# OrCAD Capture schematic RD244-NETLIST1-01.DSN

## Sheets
1 7: size Custom
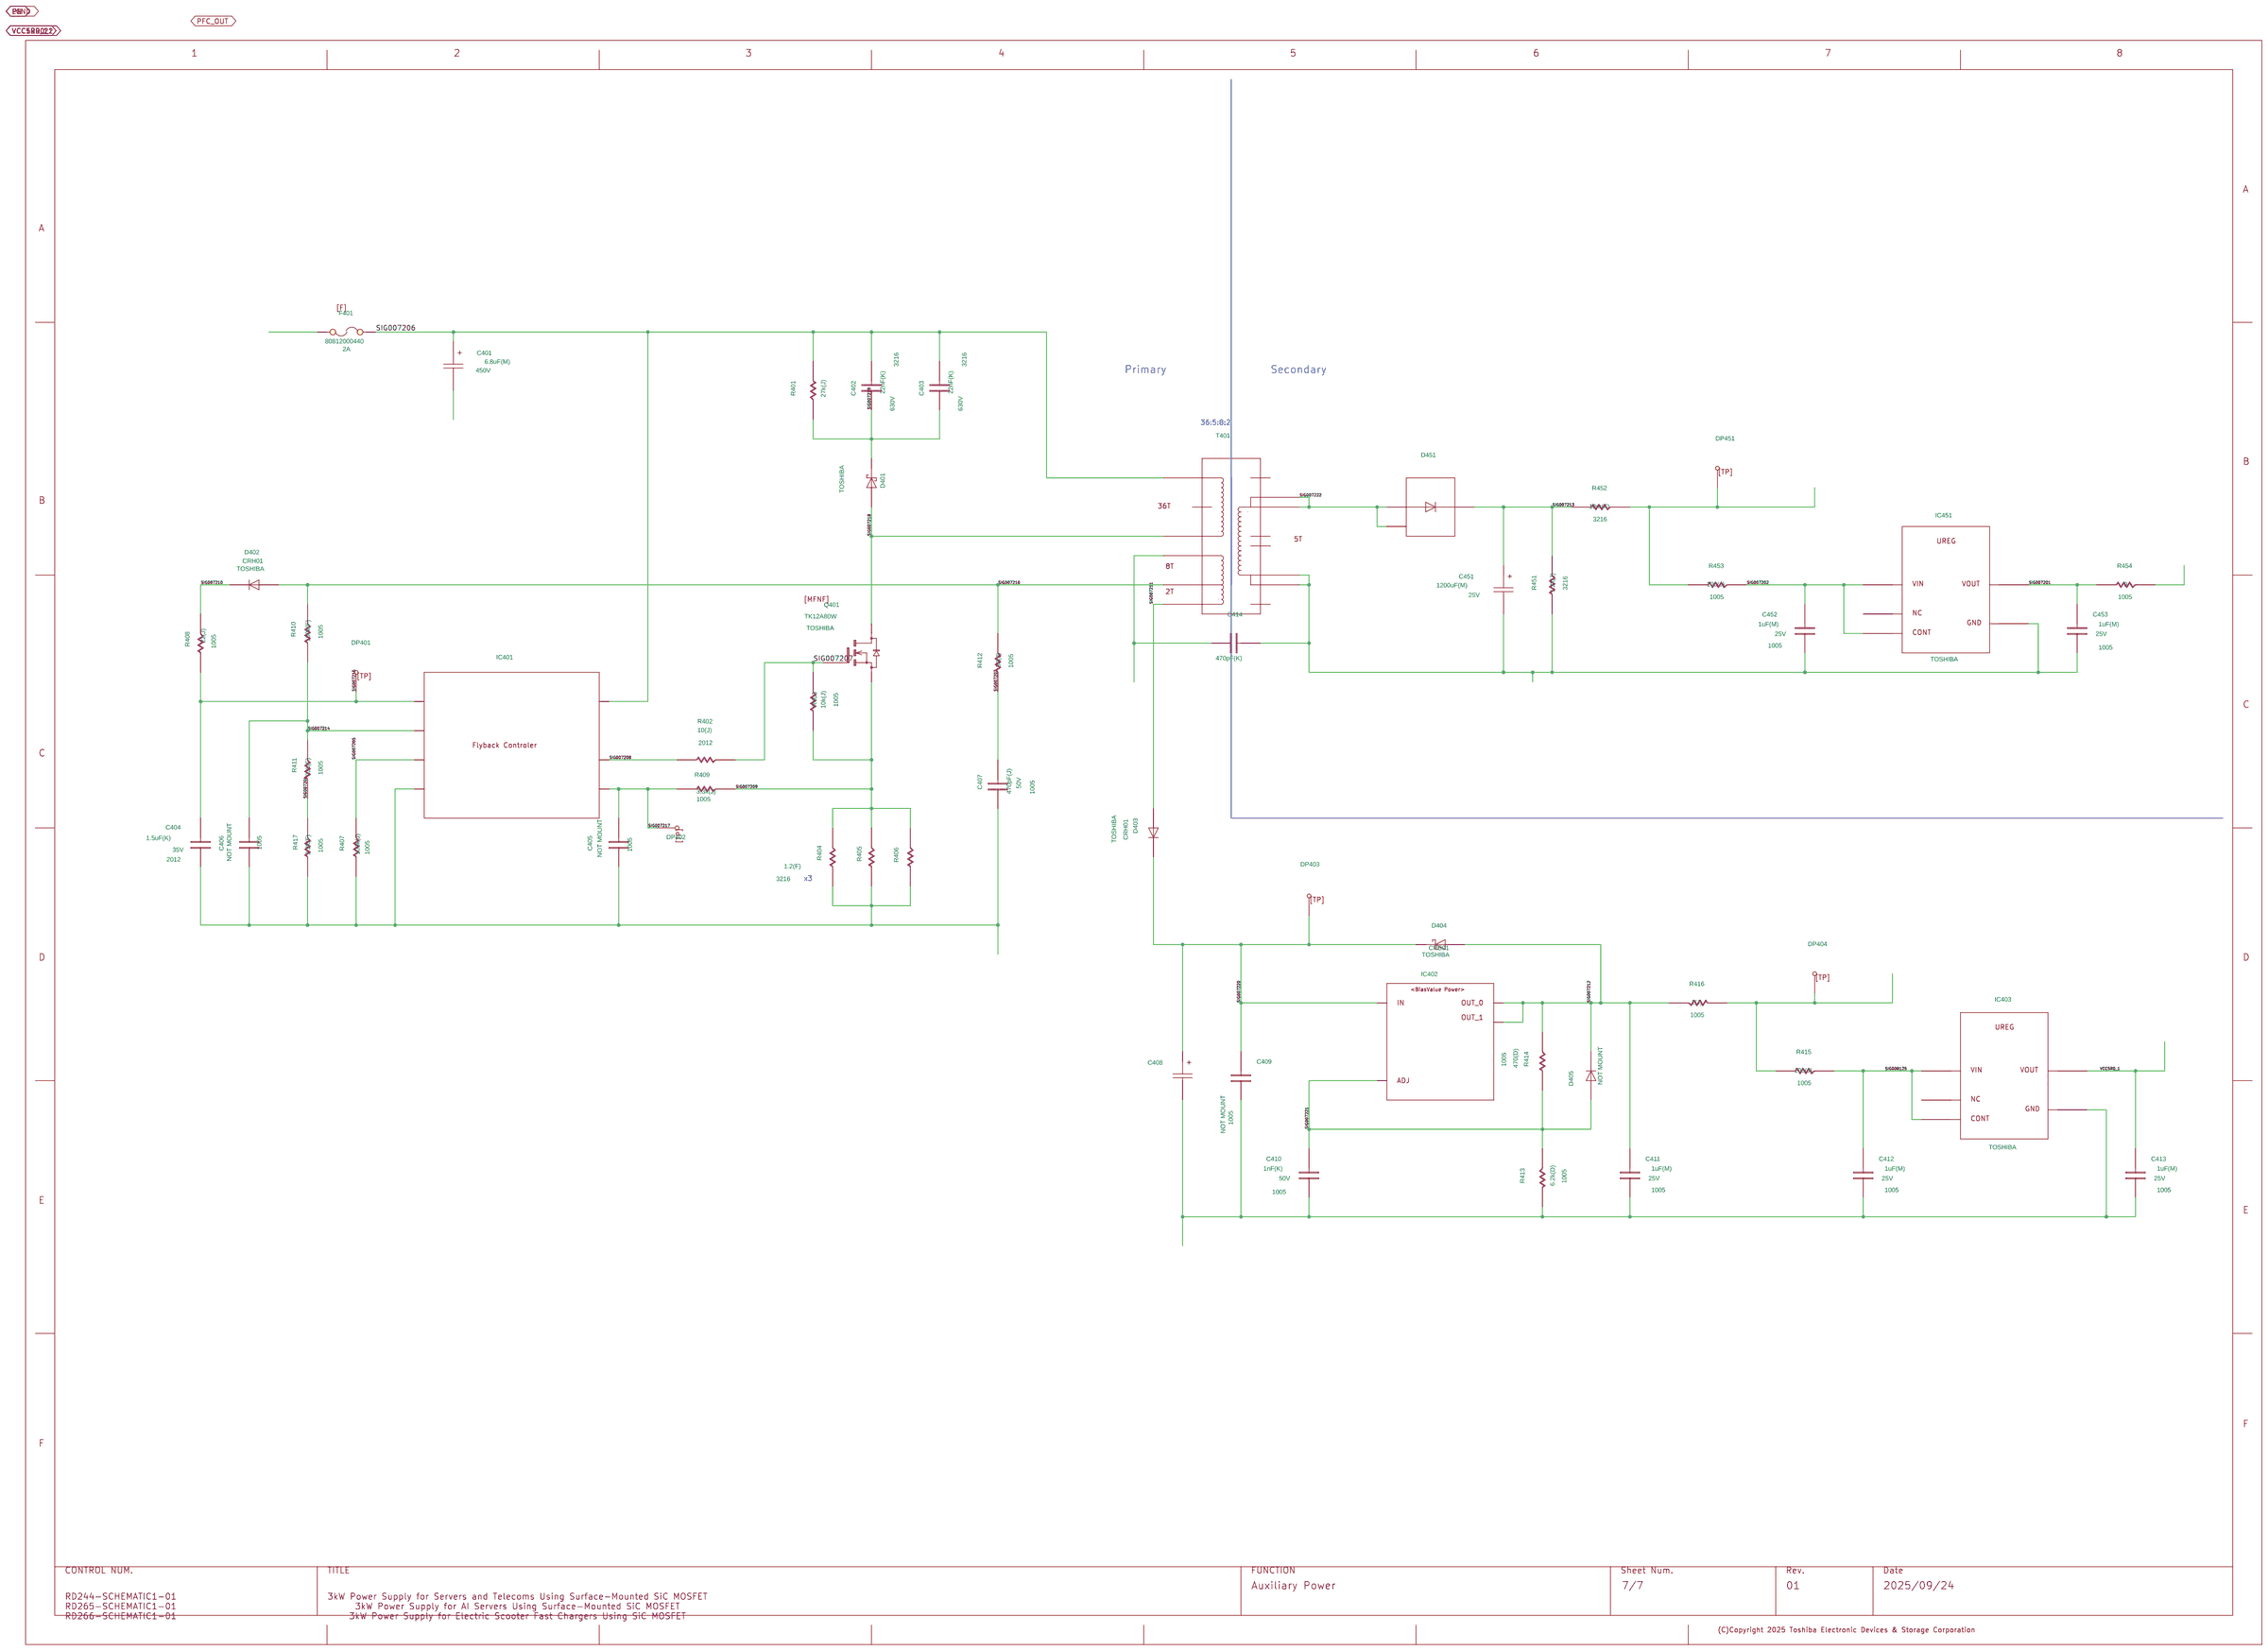
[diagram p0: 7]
2 6: size Custom
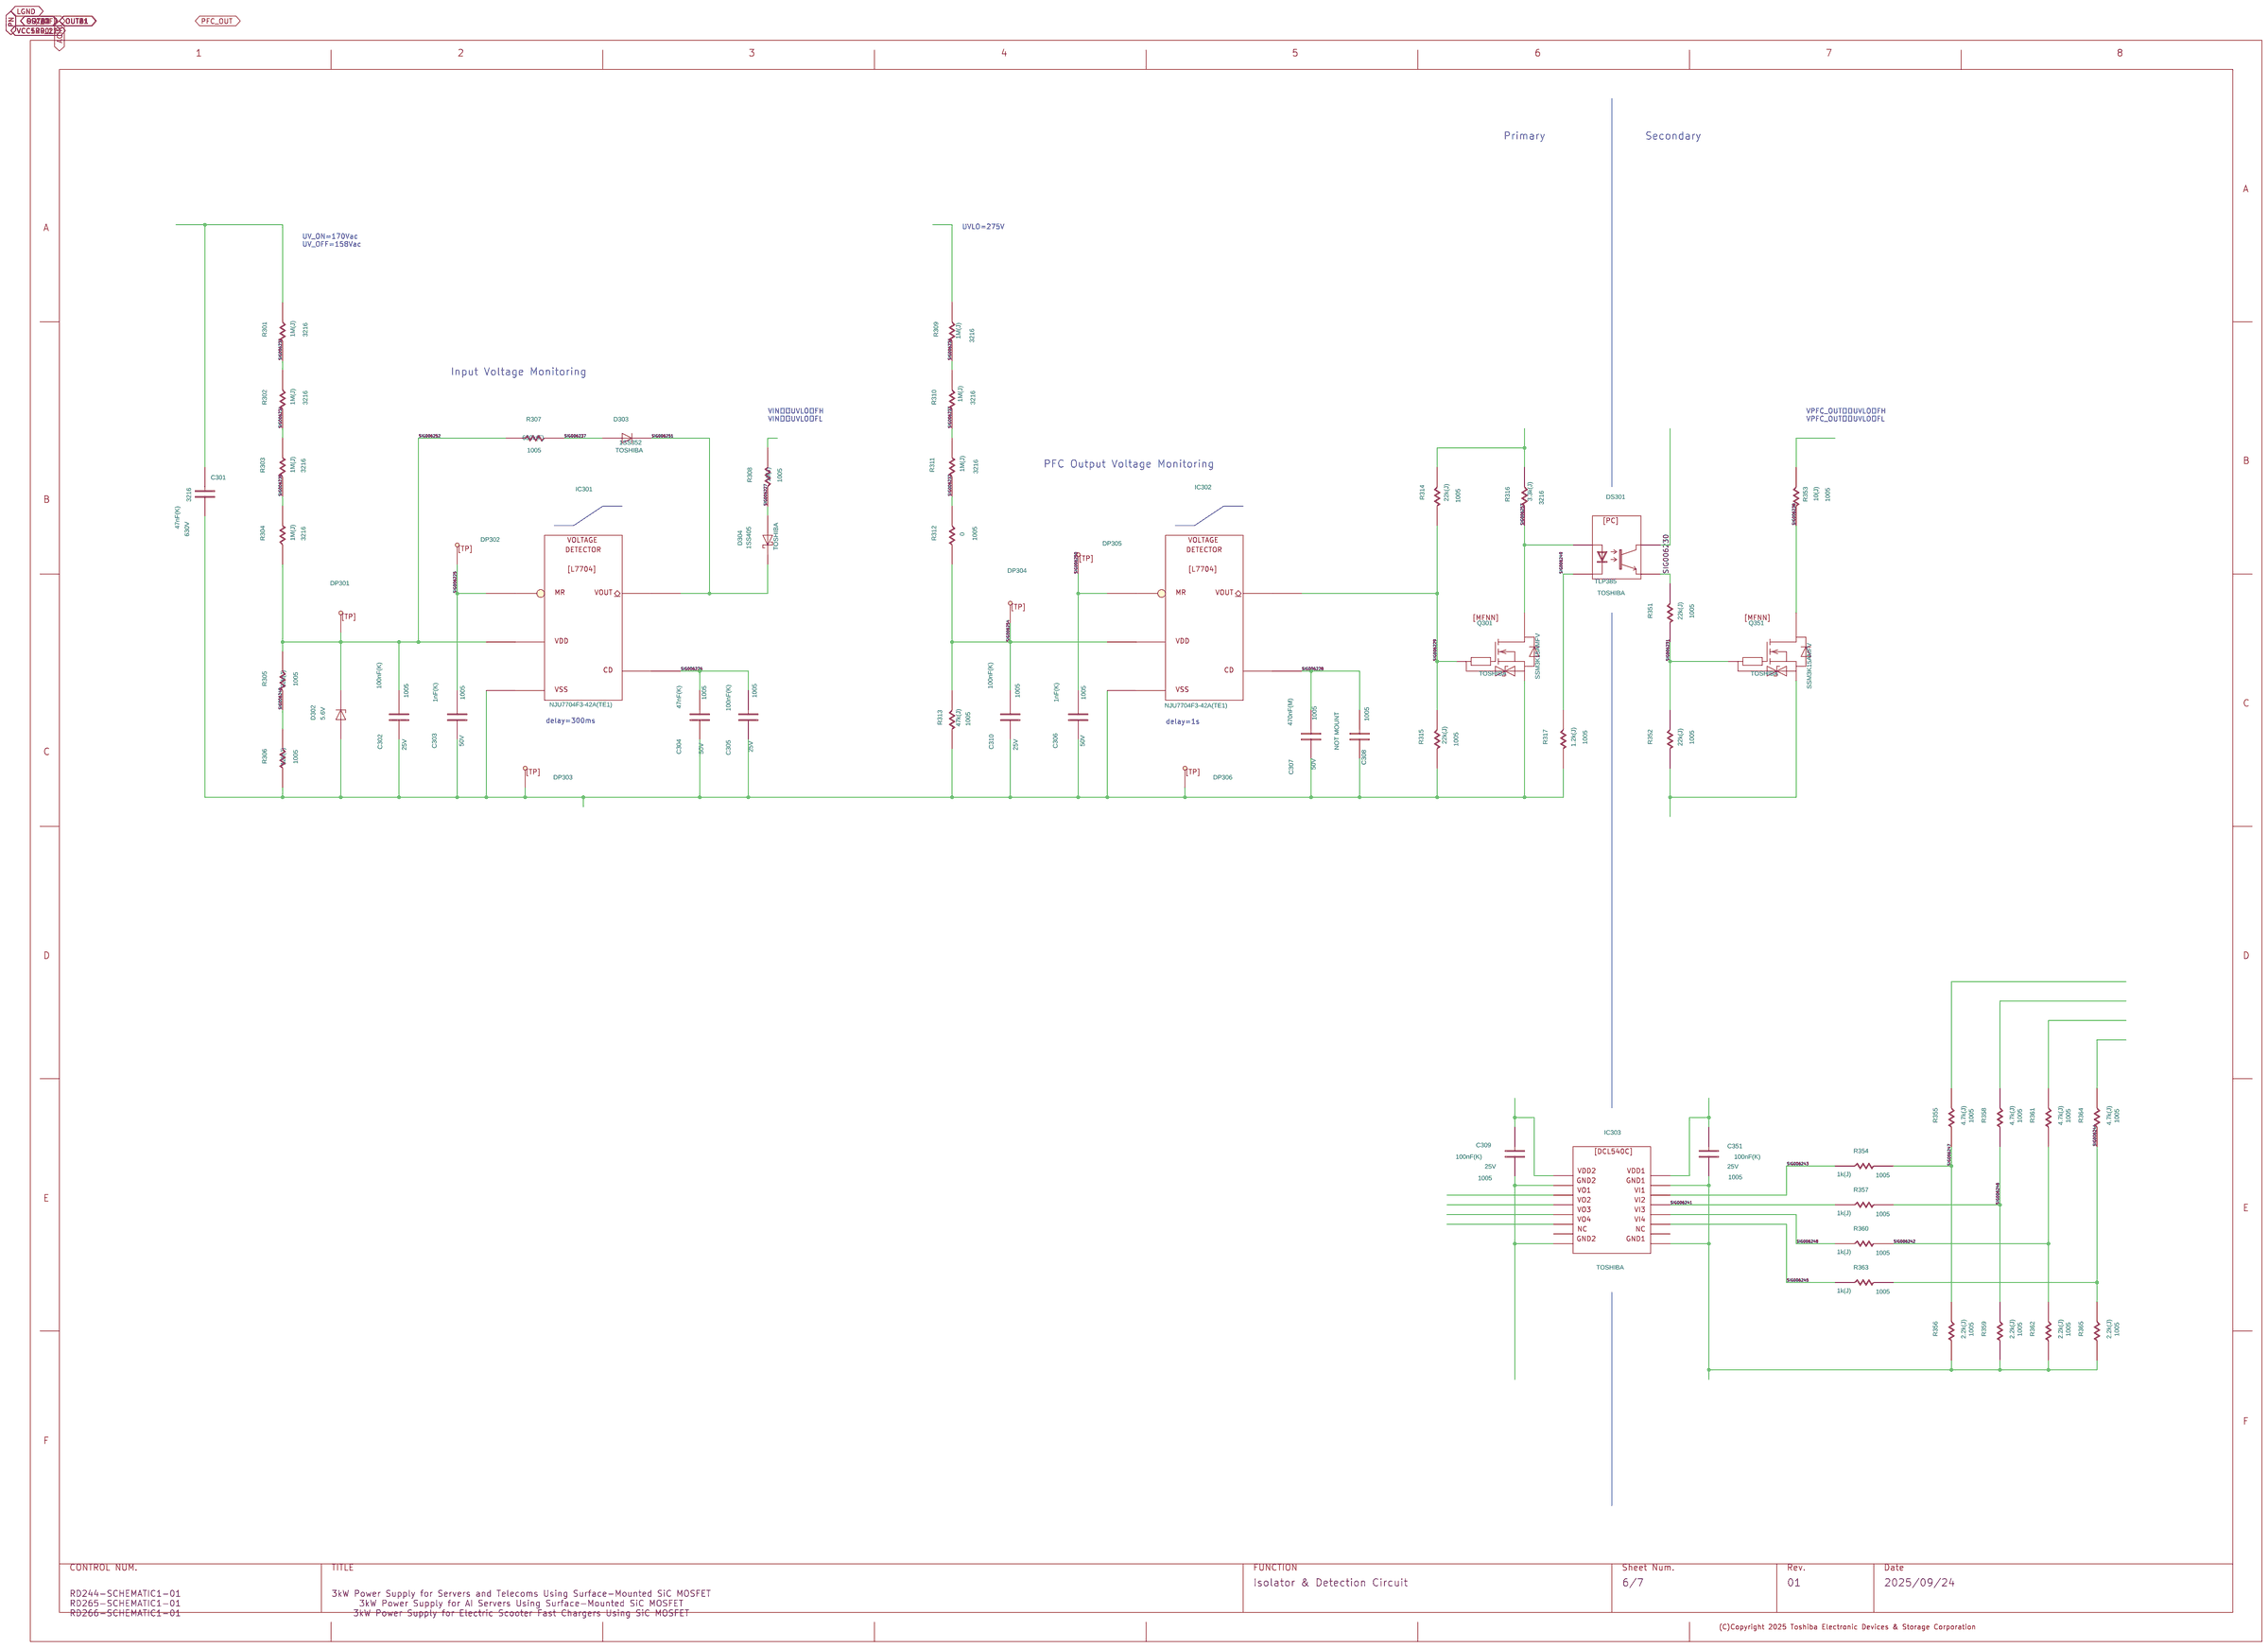
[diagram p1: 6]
3 5: size Custom
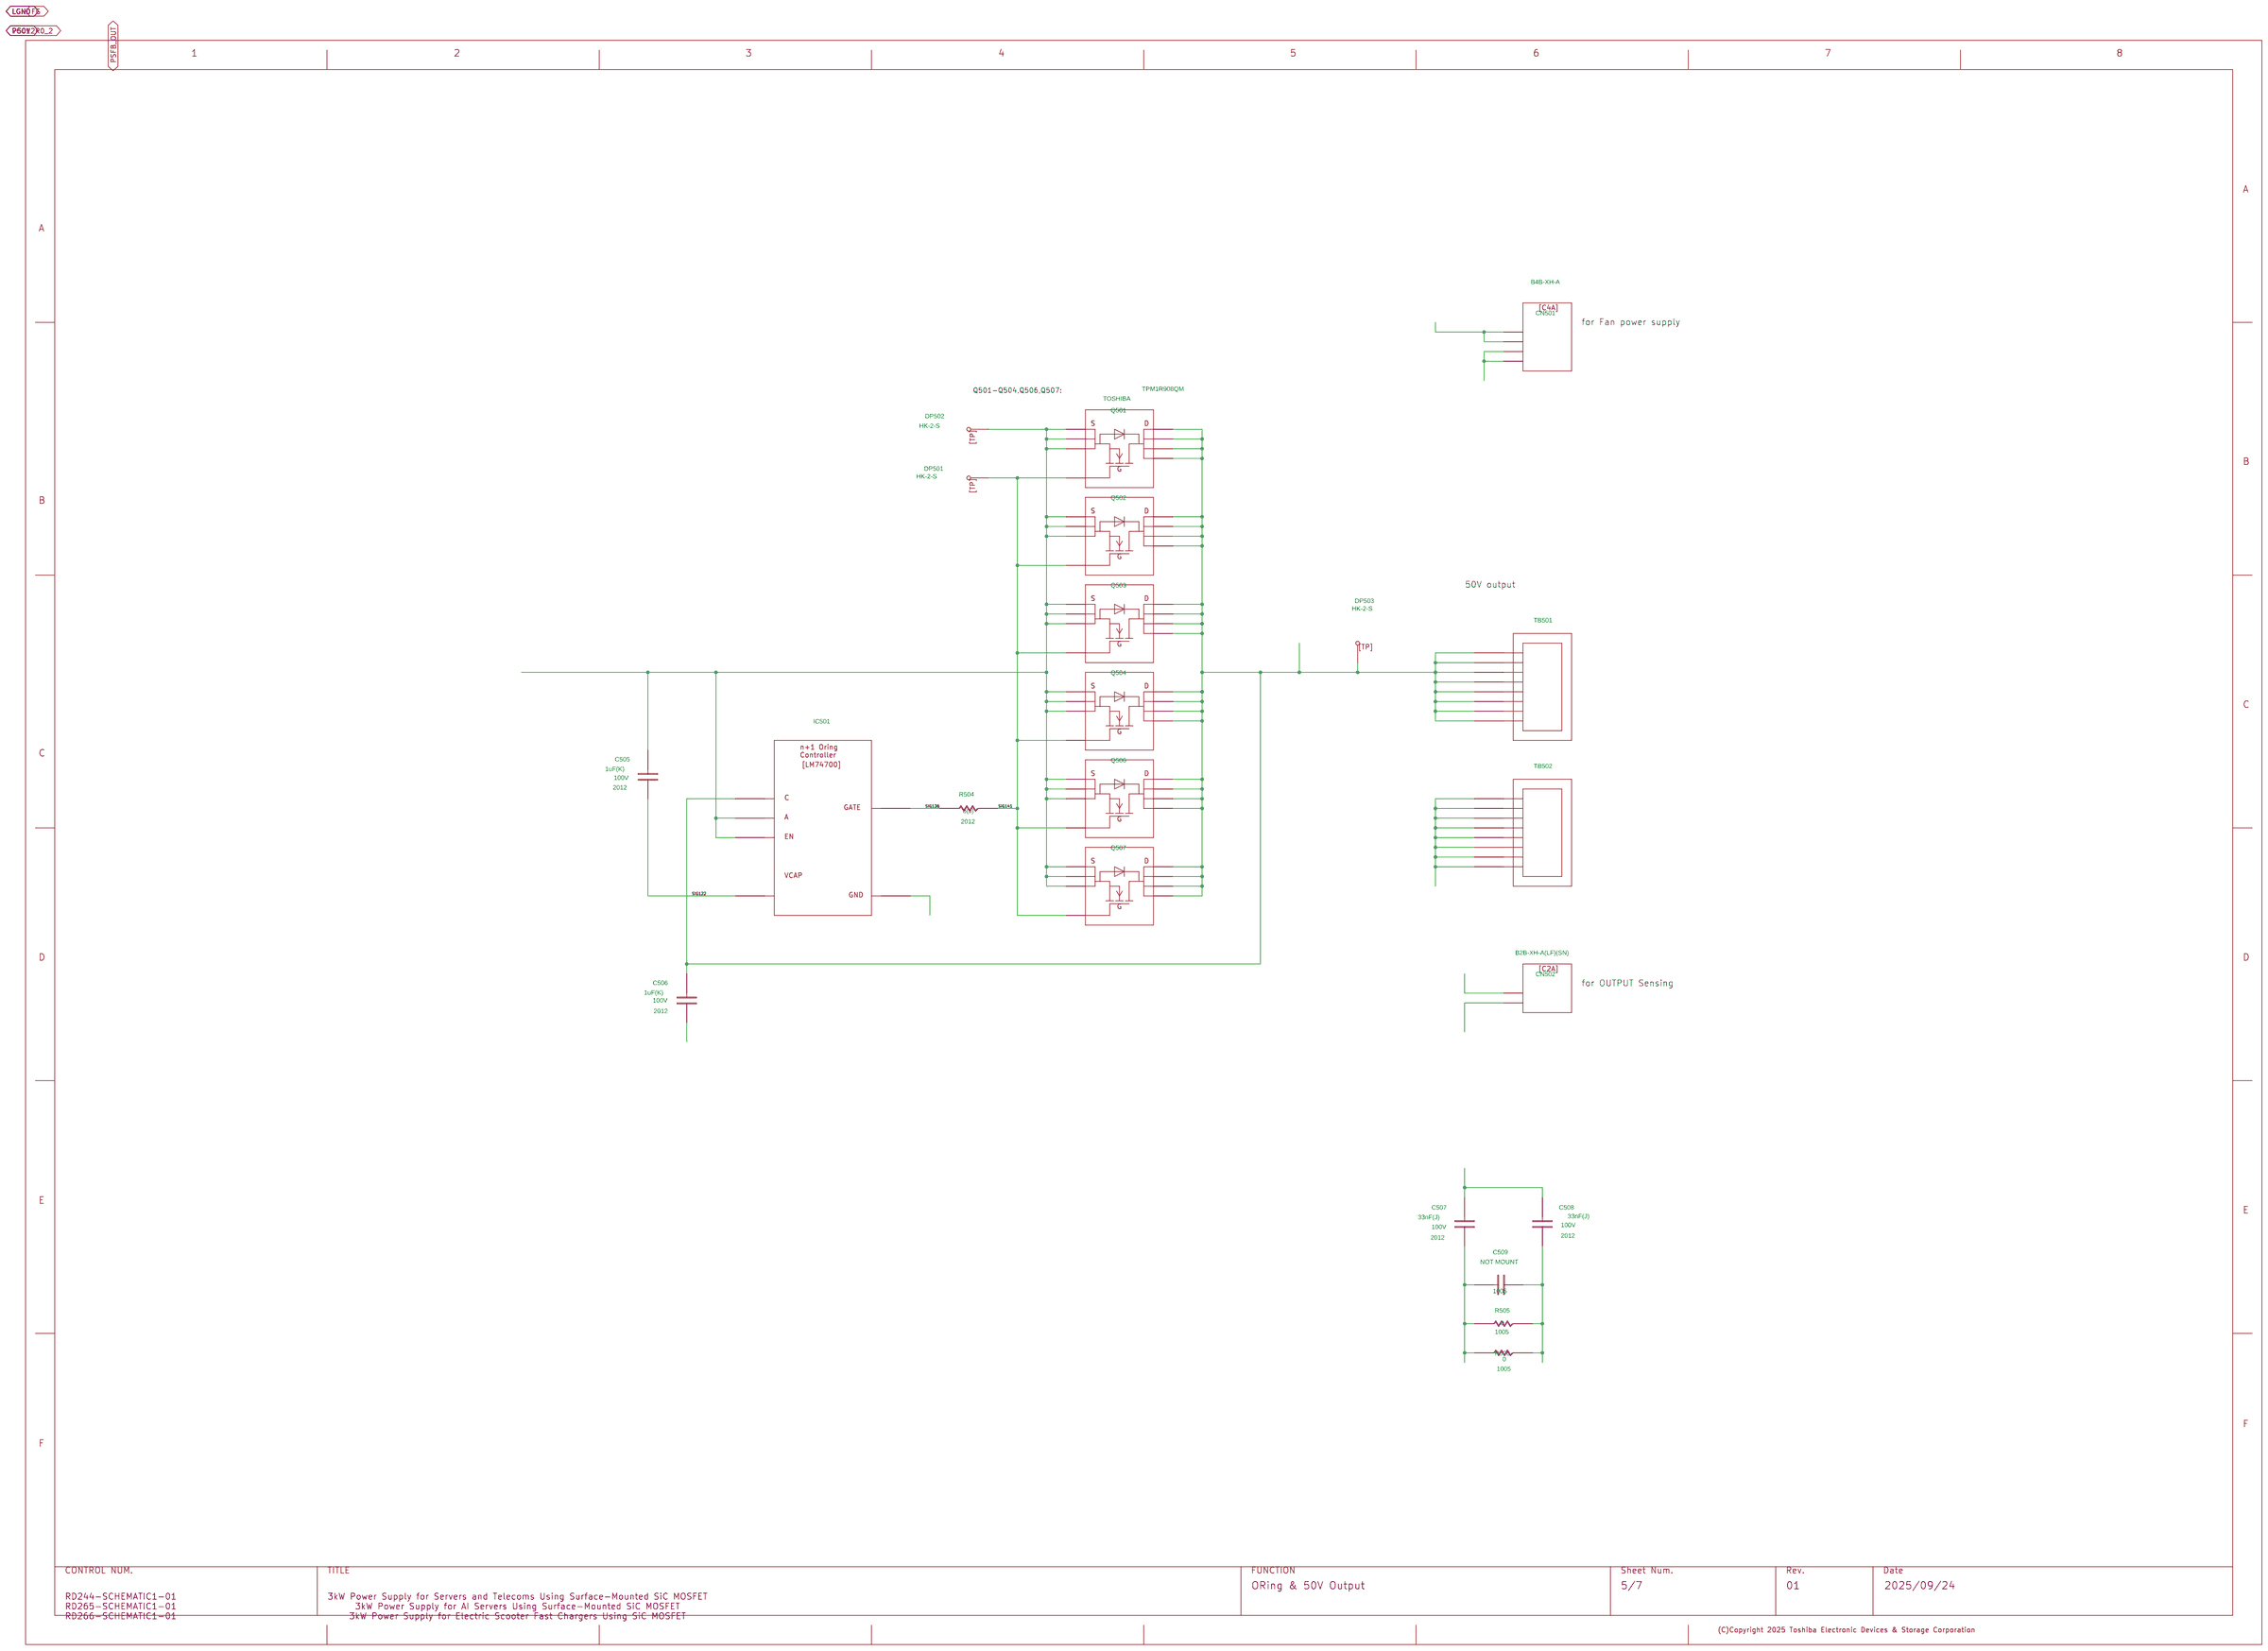
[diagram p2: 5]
4 4: size Custom
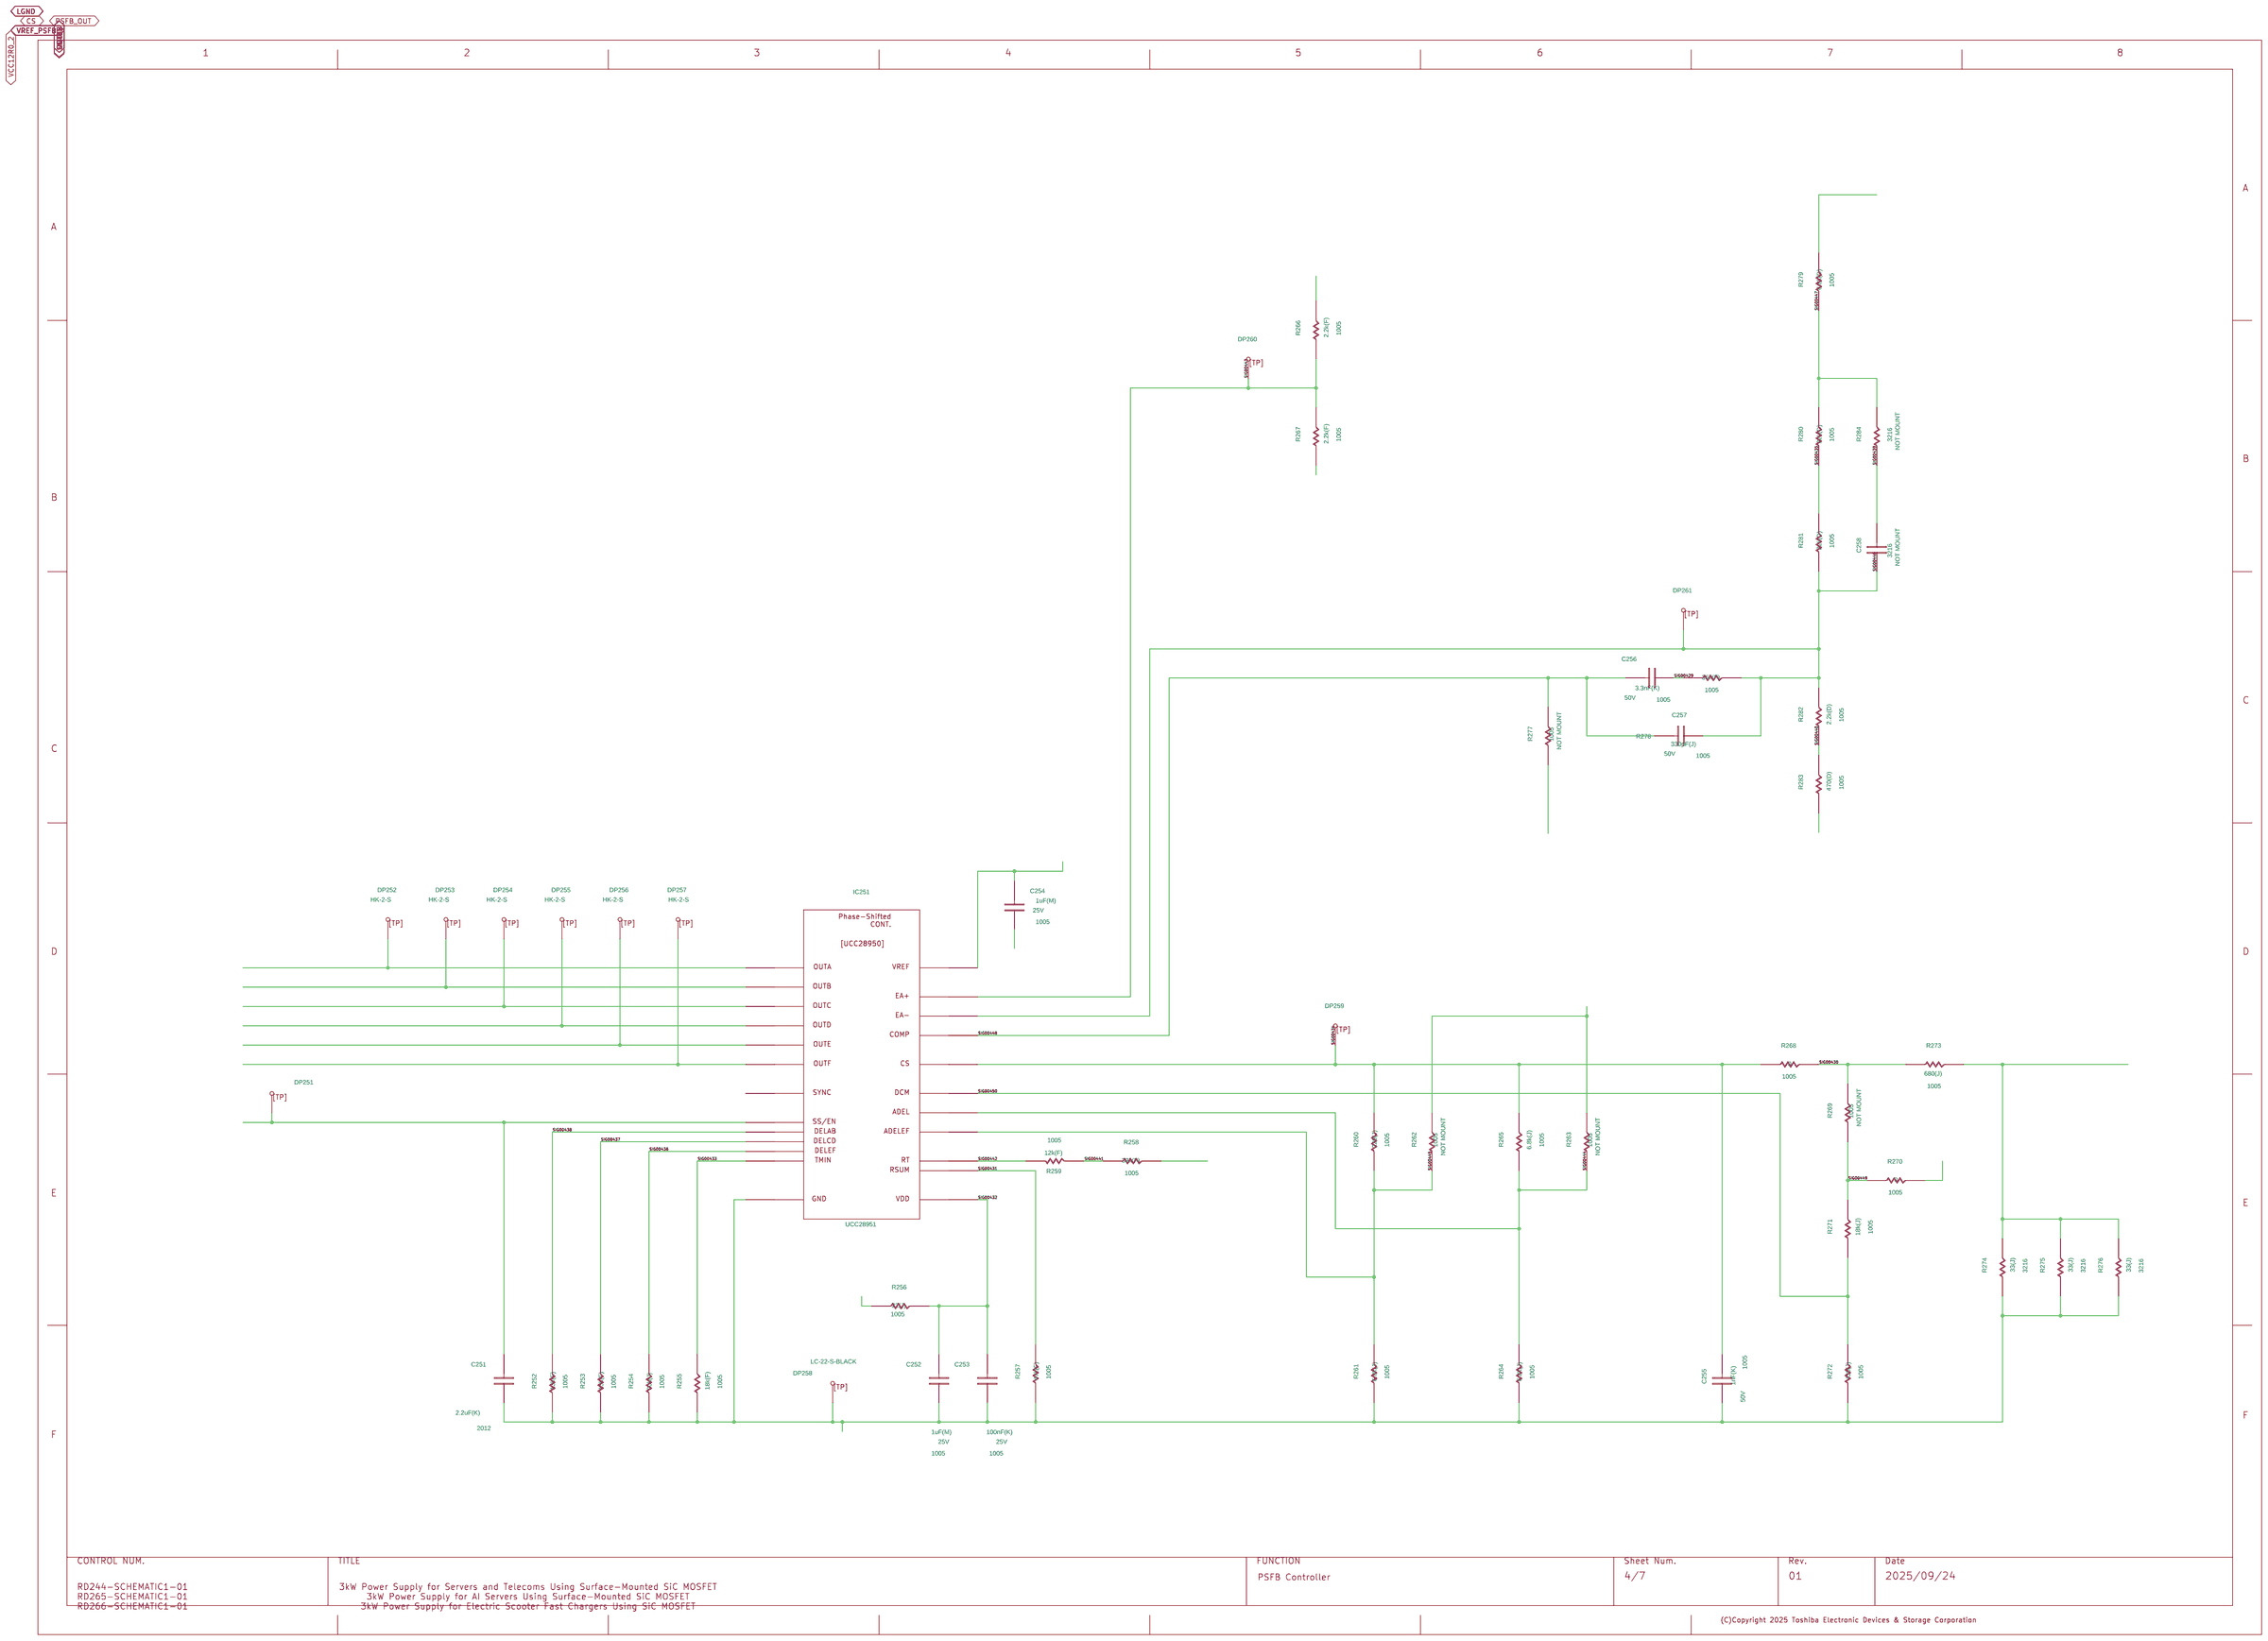
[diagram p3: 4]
5 3: size Custom
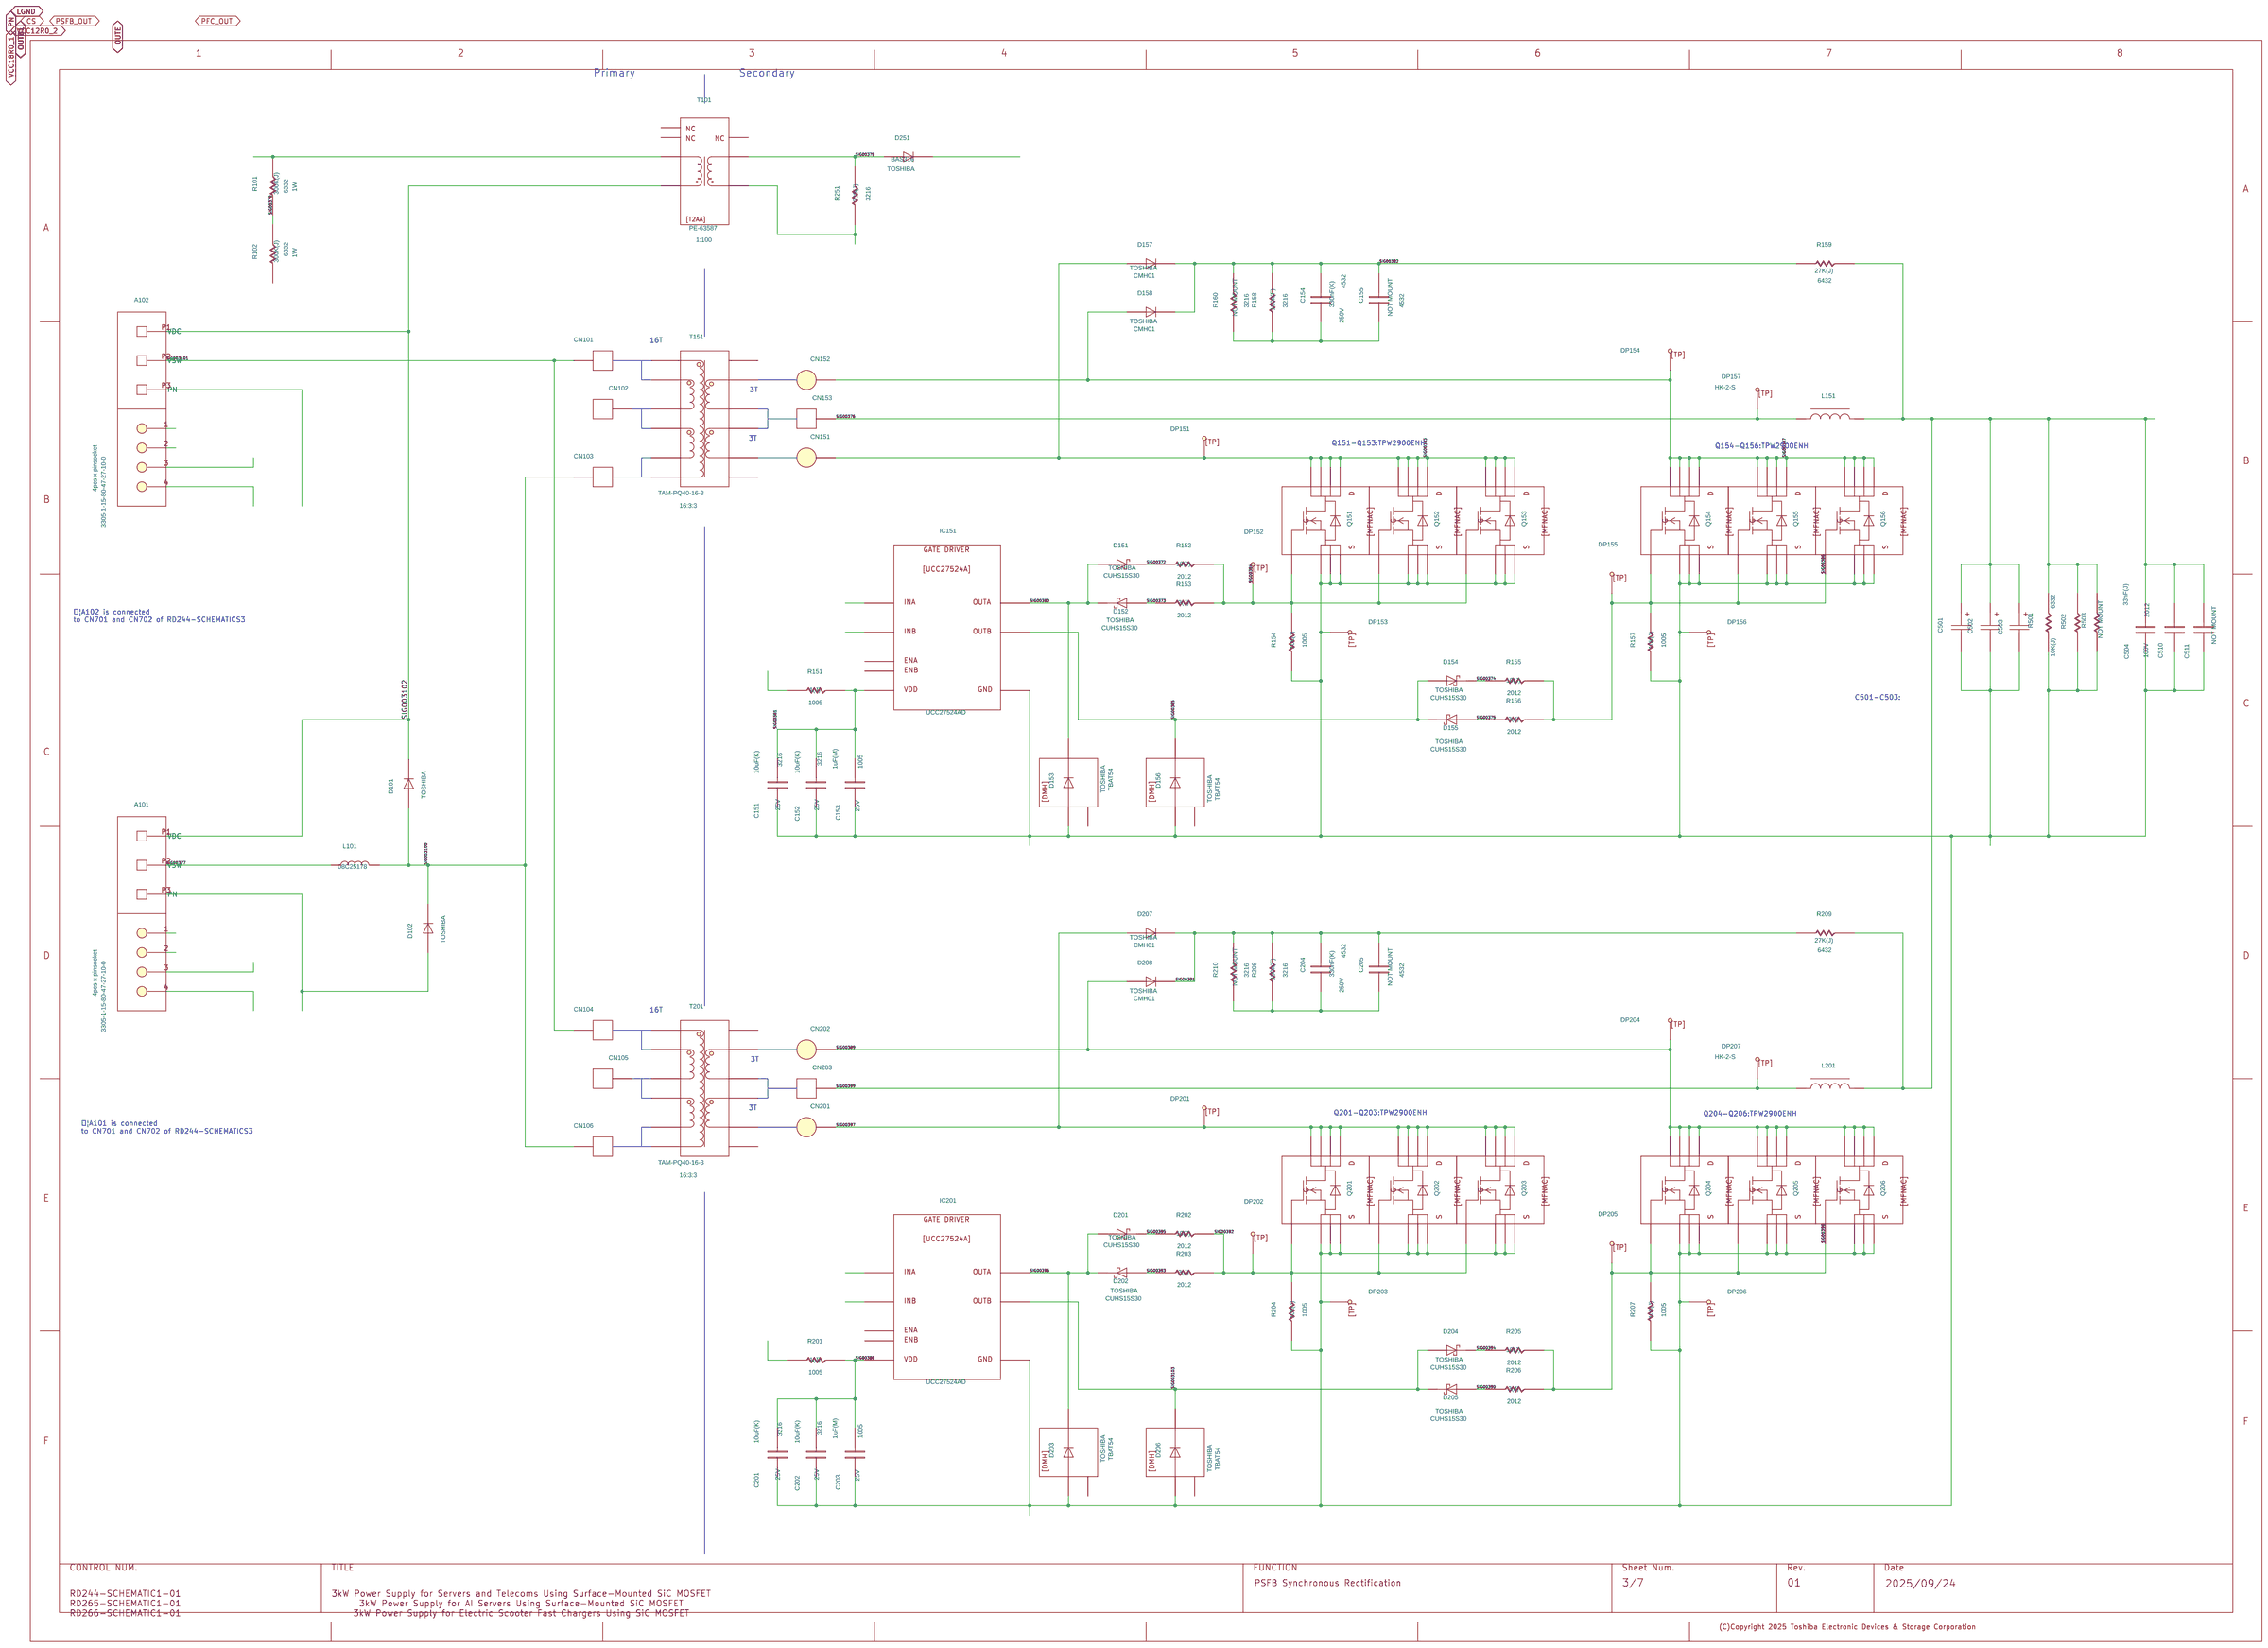
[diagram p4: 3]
6 2: size Custom
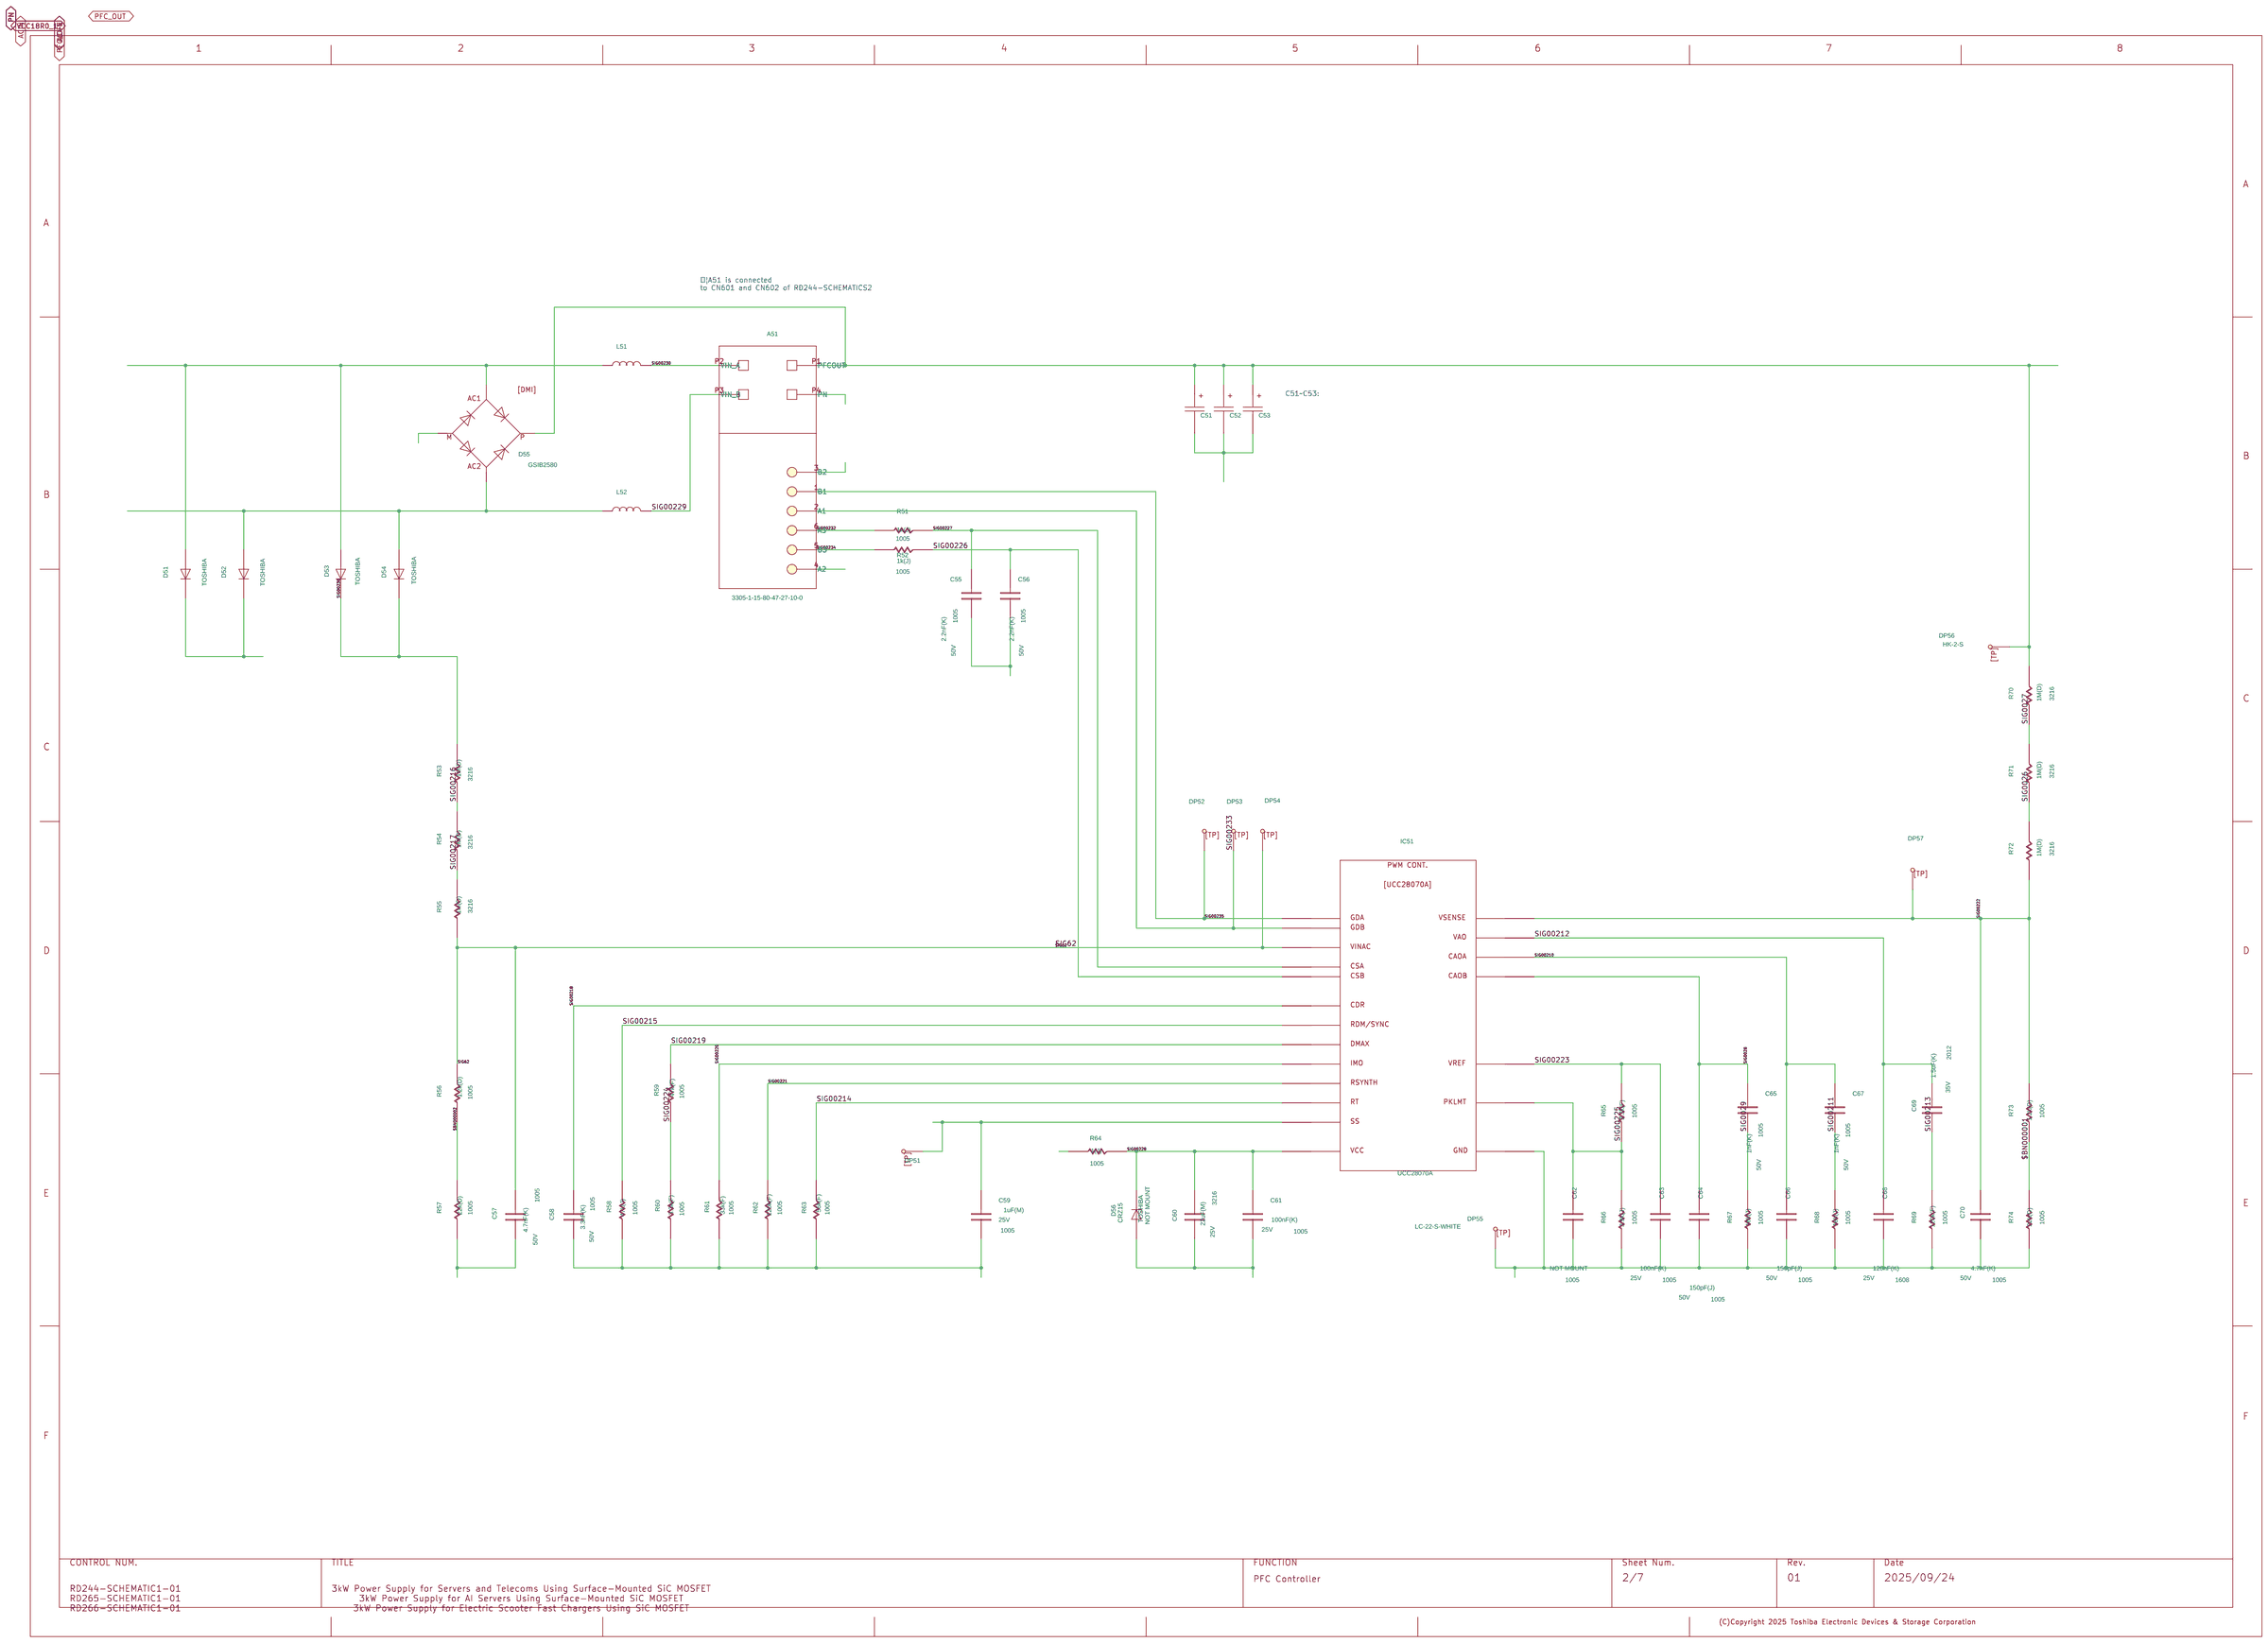
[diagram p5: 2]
7 1: size Custom
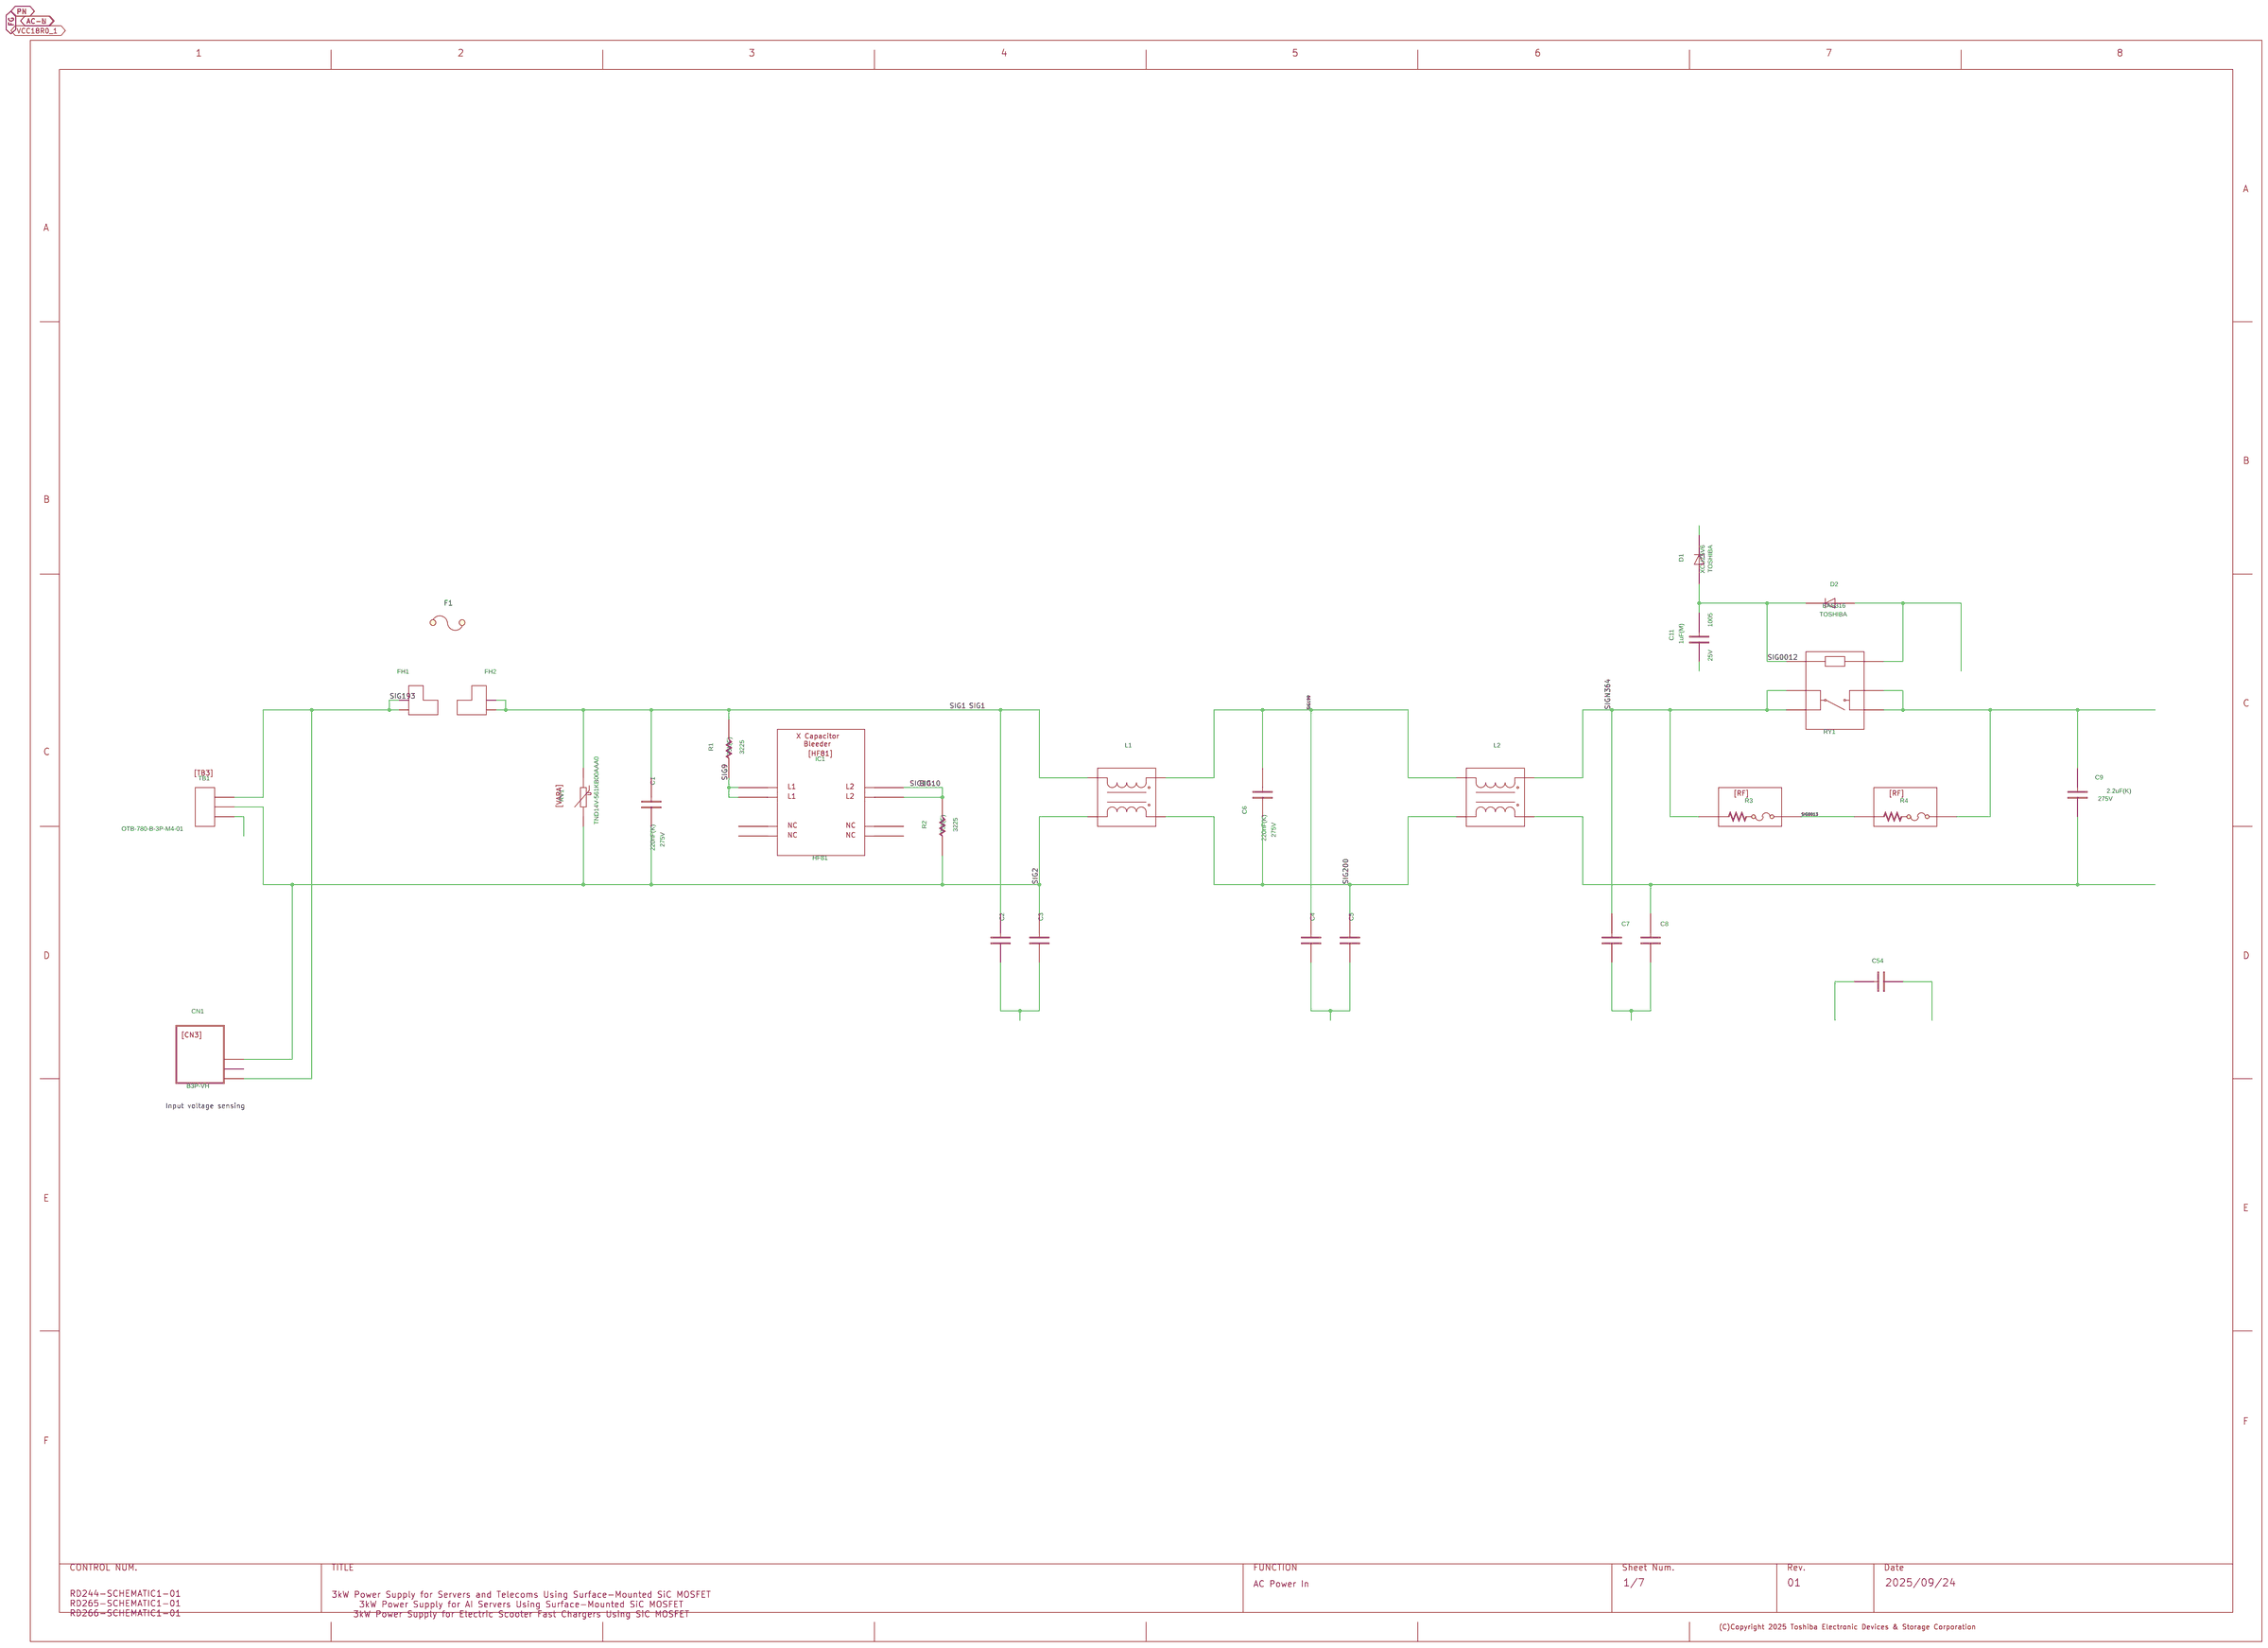
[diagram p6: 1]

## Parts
sheet 1
C1  C
C2  DE2B3SA101KA3BT02F
C3  DE2B3SA101KA3BT02F
C4  DE2E3SA222MN3AT02F
C5  DE2E3SA222MN3AT02F
C6  C
C7  DE2E3SA222MN3AT02F
C8  DE2E3SA222MN3AT02F
C9  C
C11  C
C54  DE2B3SA221KA3BT02F
CN1  CN3
D1  ZENERDIODE_USC-01
D2  D
F1  -
FH1  01220083Z
FH2  01220083Z
IC1  L81
L1  LDFW021252YBUV0E
L2  LDFW021252YBUV0E
R1  R
R2  R
R3  Y5JA-330JPTL3_5
R4  Y5JA-330JPTL3_5
RV1  VARA
RY1  G2RL-1A-E2-CV-HA
TB1  TB3
U?#6  WAKU_DEF_A3_1
sheet 2
A51  RD-244_PFC_UNIT1
C51  EKHE421VSN102MA45Z
C52  EKHE421VSN102MA45Z
C53  EKHE421VSN102MA45Z
C55  C
C56  C
C57  C
C58  C
C59  C
C60  C
C61  C
C62  C
C63  C
C64  C
C65  C
C66  C
C67  C
C68  C
C69  GRM21BC71E106KE01
C70  C
D51  CRG04A
D52  CRG04A
D53  CRG04A
D54  CRG04A
D55  DMI
D56  ZD
DP51  TP
DP52  TP
DP53  TP
DP54  TP
DP55  TP
DP56  TP
DP57  TP
IC51  L28070
L51  TAM-30A131
L52  TAM-30A131
R51  R
R52  R
R53  R
R54  R
R55  R
R56  R
R57  R
R58  R
R59  R
R60  R
R61  R
R62  R
R63  R
R64  R
R65  R
R66  R
R67  R
R68  R
R69  R
R70  R
R71  R
R72  R
R73  R
R74  R
U?#5  WAKU_DEF_A3_1
sheet 3
A101  RD-244_FB_UNIT
A102  RD-244_FB_UNIT
C151  C
C152  C
C153  C
C154  C
C155  C
C201  C
C202  C
C203  C
C204  C
C205  C
C501  CP
C502  CP
C503  CP
C504  GRM21BC71E106KE01
C510  GRM21BC71E106KE01
C511  GRM21BC71E106KE01
CN101  LONGHOLE_2R5-5R5
CN102  LONGHOLE_2R5-4R5
CN103  LONGHOLE_2R5-5R5
CN104  LONGHOLE_2R5-5R5
CN105  LONGHOLE_2R5-4R5
CN106  LONGHOLE_2R5-5R5
CN151  TH_PHI_4R5
CN152  TH_PHI_4R5
CN153  LONGHOLE_4R5-8R5
CN201  TH_PHI_4R5
CN202  TH_PHI_4R5
CN203  LONGHOLE_4R5-8R5
D101  TRS8E65F
D102  TRS8E65F
D151  CUHS15S30
D152  CUHS15S30
D153  DMH
D154  CUHS15S30
D155  CUHS15S30
D156  DMH
D157  D
D158  D
D201  CUHS15S30
D202  CUHS15S30
D203  DMH
D204  CUHS15S30
D205  CUHS15S30
D206  DMH
D207  D
D208  D
D251  D
DP151  TP
DP152  TP
DP153  TP
DP154  TP
DP155  TP
DP156  TP
DP157  TP
DP201  TP
DP202  TP
DP203  TP
DP204  TP
DP205  TP
DP206  TP
DP207  TP
IC151  L27524
IC201  L27524
L101  TMSD-Y3001
L151  TAM-CTW32A6R5
L201  TAM-CTW32A6R5
Q151  TPH2R408QM_8PIN
Q152  TPH2R408QM_8PIN
Q153  TPH2R408QM_8PIN
Q154  TPH2R408QM_8PIN
Q155  TPH2R408QM_8PIN
Q156  TPH2R408QM_8PIN
Q201  TPH2R408QM_8PIN
Q202  TPH2R408QM_8PIN
Q203  TPH2R408QM_8PIN
Q204  TPH2R408QM_8PIN
Q205  TPH2R408QM_8PIN
Q206  TPH2R408QM_8PIN
R101  R
R102  R
R151  R
R152  R
R153  R
R154  R
R155  R
R156  R
R157  R
R158  R
R159  R
R160  R
R201  R
R202  R
R203  R
R204  R
R205  R
R206  R
R207  R
R208  R
R209  R
R210  R
R251  R
R501  R
R502  R
R503  R
T101  T2AA
T151  T3_12V67A
T201  T3_12V67A
U?#4  WAKU_DEF_A3_1
sheet 4
C251  GRM21BC71E106KE01
C252  C
C253  C
C254  C
C255  C
C256  C
C257  C
C258  C
DP251  TP
DP252  TP
DP253  TP
DP254  TP
DP255  TP
DP256  TP
DP257  TP
DP258  TP
DP259  TP
DP260  TP
DP261  TP
IC251  L28950
R252  R
R253  R
R254  R
R255  R
R256  R
R257  R
R258  R
R259  R
R260  R
R261  R
R262  R
R263  R
R264  R
R265  R
R266  R
R267  R
R268  R
R269  R
R270  R
R271  R
R272  R
R273  R
R274  R
R275  R
R276  R
R277  R
R278  R
R279  R
R280  R
R281  R
R282  R
R283  R
R284  R
U?#3  WAKU_DEF_A3_1
sheet 5
C505  GRM21BC71E106KE01
C506  GRM21BC71E106KE01
C507  GRM21BC71E106KE01
C508  GRM21BC71E106KE01
C509  C
CN501  C4A
CN502  C2A
DP501  TP
DP502  TP
DP503  TP
IC501  LM74700-Q1
Q501  NCHMOSFET_SOPADVANCE-E-01
Q502  NCHMOSFET_SOPADVANCE-E-01
Q503  NCHMOSFET_SOPADVANCE-E-01
Q504  NCHMOSFET_SOPADVANCE-E-01
Q506  NCHMOSFET_SOPADVANCE-E-01
Q507  NCHMOSFET_SOPADVANCE-E-01
R504  R
R505  R
R506  R
TB501  7460305
TB502  7460305
U?#2  WAKU_DEF_A3_1
sheet 6
C301  C
C302  C
C303  C
C304  C
C305  C
C306  C
C307  C
C308  C
C309  C
C310  C
C351  C
D302  ZENERDIODE_USC-01
D303  D
D304  1SS405
DP301  TP
DP302  TP
DP303  TP
DP304  TP
DP305  TP
DP306  TP
DS301  TLP385
IC301  L7704
IC302  L7704
IC303  DCL540C01
Q301  MFNN
Q351  MFNN
R301  R
R302  R
R303  R
R304  R
R305  R
R306  R
R307  R
R308  R
R309  R
R310  R
R311  R
R312  R
R313  R
R314  R
R315  R
R316  R
R317  R
R351  R
R352  R
R353  R
R354  R
R355  R
R356  R
R357  R
R358  R
R359  R
R360  R
R361  R
R362  R
R363  R
R364  R
R365  R
U?#1  WAKU_DEF_A3_1
sheet 7
C401  CP
C402  C
C403  C
C404  GRM21BC71E106KE01
C405  C
C406  C
C407  C
C408  EMLA350ARA331MJA0G
C409  C
C410  C
C411  C
C412  C
C413  C
C414  DE2B3SA221KA3BT02F
C451  CP
C452  C
C453  C
D401  CRF03A
D402  D
D403  D
D404  SBD
D405  D
D451  RF501BGE2S
DP401  TP
DP402  TP
DP403  TP
DP404  TP
DP451  TP
F401  F
IC401  UCC28711
IC402  LM317_TRANS  [DCY0004A_N]
IC403  TCR1HF50B
IC451  TCR1HF50B
Q401  MFNF
R401  R
R402  R
R403  R
R404  R
R405  R
R406  R
R407  R
R408  R
R409  R
R410  R
R411  R
R412  R
R413  R
R414  R
R415  R
R416  R
R417  R
R451  R
R452  R
R453  R
R454  R
T401  T3_12V67A
U?#7  WAKU_DEF_A3_1

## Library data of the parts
C1 C6 = C: COMP: PRT_17; COMPONENTTYPE: 4; GCOUNT: 1; MAXGCOUNT: 1; SAVECOUNT: 0; SIZECODESMD: DIP; VAL1: 220nF(K); VAL2: 275V
C2 C3 = DE2B3SA101KA3BT02F: CHIPSIZE: [hsb`7.5mmió]; COMPONENTTYPE: 4; GCOUNT: 1; MAXGCOUNT: 1; SIZECODESMD: DIP
C4 C7 C8 = DE2E3SA222MN3AT02F: CHIPSIZE: [hsb`7.5mmió]; COMPONENTTYPE: 4; GCOUNT: 1; MAXGCOUNT: 1; SIZECODESMD: DIP
C5 = DE2E3SA222MN3AT02F: ADSCNVFLAG: ON; CHIPSIZE: [hsb`7.5mmió]; COMPONENTTYPE: 4; GCOUNT: 1; ICX_PART_MODEL: CON_2.2N; MAXGCOUNT: 1; SIZECODESMD: DIP; SQ_PART_MODEL: CON_2.2N
C9 = C: COMP: PRT_18; COMPONENTTYPE: 4; GCOUNT: 1; MAXGCOUNT: 1; SAVECOUNT: 0; SIZECODESMD: DIP; VAL1: 2.2uF(K); VAL2: 275V
C11 C59 C153 C203 C252 C254 = C: CHIPSIZE: 1005; COMP: PRT_52; COMPONENTTYPE: 4; GCOUNT: 1; MAXGCOUNT: 1; SAVECOUNT: 0; SIZECODESMD: 1005; VAL1: 1uF(M); VAL2: 25V
C54 = DE2B3SA221KA3BT02F: COMPONENTTYPE: 4; GCOUNT: 1; MAXGCOUNT: 1; SIZECODESMD: DIP
CN1 = CN3: ADSCNVFLAG: ON; CDBNAME: G36220401068; COMP: G36220401068; COMPONENTNAME: G36220401068_package; COMPONENTTYPE: 4; FUNCN: G36220401068; GCOUNT: 1; MAXGCOUNT: 1; SAVECOUNT: 0; USERCOMPTEXT3: [JCY; VAL3: B3P-VH
D1 = ZENERDIODE_USC-01: ADSCNVFLAG: ON; ADSCOMPONENTNAME: D_ZD; COMPONENTTYPE: 4; GCOUNT: 1; MAXGCOUNT: 1; USERCOMPTEXT3: TOSHIBA; VAL1: 5.6V; VAL3: XCUZ5V6
D2 = D: COMP: PRT_26; COMPONENTTYPE: 4; GCOUNT: 1; MAXGCOUNT: 1; USERCOMPTEXT2: 100V,0.25A; USERCOMPTEXT3: TOSHIBA; VAL3: BAS316
F1 = 0326030.MXP: COMPONENTTYPE: 4
FH1 FH2 = 01220083Z: COMPONENTTYPE: 4
IC1 = L81: COMP: PRT_45; COMPONENTTYPE: 4; VAL3: HF81
L1 L2 = LDFW021252YBUV0E: COMPONENTTYPE: 4
R1 R2 = R: CHIPSIZE: 3225; COMP: PRT_23; COMPONENTTYPE: 4; GCOUNT: 1; MAXGCOUNT: 1; SAVECOUNT: 0; SIZECODESMD: 3225; VAL1: 75k(F); VAL2: 500mW
R3 R4 = Y5JA-330JPTL3_5: CHIPSIZE: 13x9xH25.5; COMPONENTTYPE: 4; GCOUNT: 1; MAXGCOUNT: 1
RV1 = VARA: COMP: PRT_37; COMPONENTTYPE: 4; GCOUNT: 1; MAXGCOUNT: 1; VAL1: 560V; VAL3: TND14V-561KB00AAA0
RY1 = G2RL-1A-E2-CV-HA: COMPONENTTYPE: 4; GCOUNT: 1; MAXGCOUNT: 1; SAVEAREA0: -9347,-440,34039,23986; USERCOMPTEXT1: 23A
TB1 = TB3: ADSCNVFLAG: ON; COMP: K29S000A; COMPONENTTYPE: 4; GCOUNT: 1; MAXGCOUNT: 1; USERCOMPTEXT3: [JCY; VAL3: OTB-780-B-3P-M4-01
U?#6 = WAKU_DEF_A3_1: COMPONENTTYPE: 2; DATE: 2025/09/24; DESIGNED: TOSHIBA; DRAWINGNUMBER: RD244-SCHEMATIC1-01 / RD265-SCHEMATIC1-01 / RD266-SCHEMATIC1-01; FUNCTION: AC Power In; PAGENUMBER: 1; REVISION: 01; SAVECOUNT: 3; SHEETNUMBER: 1/7; SHTSAVECOUNT: 118; TIME: 10:19:22; TITLE: 3kW Power Supply for Servers and Telecoms Using Surface-Mounted SiC MOSFET / 3kW Power Supply for AI Servers Using Surface-Mounted SiC MOSFET / 3kW Power Supply for Electric Scooter Fast Chargers Using SiC MOSFET; UPDATEDATE: 2025.9.25; UPDATETIME: 13:12:48; UPDATEUSER: t5459927
A51 = RD-244_PFC_UNIT1: COMPONENTTYPE: 4; VAL3: 3305-1-15-80-47-27-10-0
C51-C53 = EKHE421VSN102MA45Z: ADSCNVFLAG: ON; COMPONENTTYPE: 4; GCOUNT: 1; ICX_PART_MODEL: CON_390U; MAXGCOUNT: 1; SIZECODESMD: DIP; SQ_PART_MODEL: CON_390U
C55 = C: CHIPSIZE: 1005; COMP: PRT_52; COMPONENTTYPE: 4; GCOUNT: 1; MAXGCOUNT: 1; SAVECOUNT: 0; SIZECODESMD: 1005; VAL1: 2.2nF(K); VAL2: 50V
C56 = C: CHIPSIZE: 1005; COMP: PRT_52; COMPONENTTYPE: 4; GCOUNT: 1; MAXGCOUNT: 1; OLDCOMPONENTID: 99; SAVECOUNT: 0; SIZECODESMD: 1005; VAL1: 2.2nF(K); VAL2: 50V
C57 C70 = C: CHIPSIZE: 1005; COMP: PRT_52; COMPONENTTYPE: 4; GCOUNT: 1; MAXGCOUNT: 1; SAVECOUNT: 0; SIZECODESMD: 1005; VAL1: 4.7nF(K); VAL2: 50V
C58 = C: CHIPSIZE: 1005; COMP: PRT_52; COMPONENTTYPE: 4; GCOUNT: 1; MAXGCOUNT: 1; SAVECOUNT: 0; SIZECODESMD: 1005; VAL1: 3.3nF(K); VAL2: 50V
C60 = C: COMP: PRT_46; COMPONENTTYPE: 4; SAVECOUNT: 0; SIZECODESMD: 3216; VAL1: 22uF(M); VAL2: 25V
C61 C302 C305 C309 C310 C351 = C: ADSCNVFLAG: ON; ADSCOMPONENTNAME: C_1005; CHIPSIZE: 1005; COMP: PRT_52; COMPONENTTYPE: 4; GCOUNT: 1; ICX_PART_MODEL: CON_100N; MAXGCOUNT: 1; SAVECOUNT: 0; SIZECODESMD: 1005; SQ_PART_MODEL: CON_100N; VAL1: 100nF(K); VAL2: 25V
C62 C509 = C: CHIPSIZE: 1005; COMP: PRT_52; COMPONENTTYPE: 4; GCOUNT: 1; MAXGCOUNT: 1; NOTMOUNT: NOT MOUNT; SAVECOUNT: 0; SIZECODESMD: 1005; VAL1: 100nF(K); VAL2: 25V
C63 C253 = C: CHIPSIZE: 1005; COMP: PRT_52; COMPONENTTYPE: 4; GCOUNT: 1; MAXGCOUNT: 1; SAVECOUNT: 0; SIZECODESMD: 1005; VAL1: 100nF(K); VAL2: 25V
C64 C66 = C: CHIPSIZE: 1005; COMP: PRT_52; COMPONENTTYPE: 4; GCOUNT: 1; MAXGCOUNT: 1; SAVECOUNT: 0; SIZECODESMD: 1005; VAL1: 150pF(J); VAL2: 50V
C65 C67 C255 C303 C306 = C: CHIPSIZE: 1005; COMP: PRT_52; COMPONENTTYPE: 4; GCOUNT: 1; MAXGCOUNT: 1; SAVECOUNT: 0; SIZECODESMD: 1005; VAL1: 1nF(K); VAL2: 50V
C68 = C: CHIPSIZE: 1608; COMP: PRT_48; COMPONENTTYPE: 4; GCOUNT: 1; MAXGCOUNT: 1; SAVECOUNT: 0; SIZECODESMD: 1608; VAL1: 120nF(K); VAL2: 25V
C69 C404 = GRM21BC71E106KE01: CHIPSIZE: 1005; COMPONENTTYPE: 4; GCOUNT: 1; MAXGCOUNT: 1; SIZECODESMD: 2012; VAL1: 1.5uF(K); VAL2: 35V
D51-D54 = CRG04A: COMPONENTTYPE: 4; GCOUNT: 1; MAXGCOUNT: 1; USERCOMPTEXT2: 600V,1A; USERCOMPTEXT3: TOSHIBA
D55 = DMI: COMP: PRT_53; COMPONENTTYPE: 4; GCOUNT: 1; MAXGCOUNT: 1; VAL3: GSIB2580
D56 = ZD: COMP: PRT_6; COMPONENTTYPE: 4; GCOUNT: 1; MAXGCOUNT: 1; NOTMOUNT: NOT MOUNT; USERCOMPTEXT3: TOSHIBA; VAL1: CRZ15; VAL3: CRZ15
DP51-DP54 DP57 DP151-DP156 DP201-DP206 DP251 DP259-DP261 DP301-DP306 DP401-DP404 DP451 = TP: COMP: DTP815; COMPONENTTYPE: 4; USERCOMPTEXT1: ƒ³1.5mm
DP55 = TP: COMP: PRT_49; COMPONENTTYPE: 4; VAL3: LC-22-S-WHITE
DP56 DP157 DP207 DP252-DP257 DP501-DP503 = TP: COMP: PRT_44; COMPONENTTYPE: 4; VAL3: HK-2-S
IC51 = L28070: COMP: PRT_59; COMPONENTTYPE: 4; VAL3: UCC28070A
L51 L52 = TAM-30A131: COMPONENTTYPE: 4; GCOUNT: 1; MAXGCOUNT: 1
R51 = R: CHIPSIZE: 1608; COMP: GDM010004481; COMPONENTTYPE: 4; GCOUNT: 1; MAXGCOUNT: 1; OLDCOMPONENTID: 100; SAVECOUNT: 0; SIZECODESMD: 1005; VAL1: 1k(J); VAL2: 63mW
R52 R354 R357 R360 R363 = R: CHIPSIZE: 1608; COMP: GDM010004481; COMPONENTTYPE: 4; GCOUNT: 1; MAXGCOUNT: 1; SAVECOUNT: 0; SIZECODESMD: 1005; VAL1: 1k(J); VAL2: 63mW
R53-R55 R70-R72 = R: CHIPSIZE: 1608; COMP: PRT_5; COMPONENTTYPE: 4; GCOUNT: 1; MAXGCOUNT: 1; SAVECOUNT: 0; SIZECODESMD: 3216; VAL1: 1M(D); VAL2: 250mW
R56 R73 = R: CHIPSIZE: 1608; COMP: GDM010004481; COMPONENTTYPE: 4; GCOUNT: 1; MAXGCOUNT: 1; SAVECOUNT: 0; SIZECODESMD: 1005; VAL1: 1.2k(D); VAL2: 63mW
R57 R74 R280 R281 = R: CHIPSIZE: 1608; COMP: GDM010004481; COMPONENTTYPE: 4; GCOUNT: 1; MAXGCOUNT: 1; SAVECOUNT: 0; SIZECODESMD: 1005; VAL1: 22k(D); VAL2: 63mW
R58 R313 = R: CHIPSIZE: 1608; COMP: GDM010004481; COMPONENTTYPE: 4; GCOUNT: 1; MAXGCOUNT: 1; SAVECOUNT: 0; SIZECODESMD: 1005; VAL1: 47k(J); VAL2: 63mW
R59 R257 = R: CHIPSIZE: 1608; COMP: GDM010004481; COMPONENTTYPE: 4; GCOUNT: 1; MAXGCOUNT: 1; SAVECOUNT: 0; SIZECODESMD: 1005; VAL1: 47k(F); VAL2: 63mW
R60 R65 = R: CHIPSIZE: 1608; COMP: GDM010004481; COMPONENTTYPE: 4; GCOUNT: 1; MAXGCOUNT: 1; SAVECOUNT: 0; SIZECODESMD: 1005; VAL1: 3.3k(F); VAL2: 63mW
R61 R258 = R: CHIPSIZE: 1608; COMP: GDM010004481; COMPONENTTYPE: 4; GCOUNT: 1; MAXGCOUNT: 1; SAVECOUNT: 0; SIZECODESMD: 1005; VAL1: 33k(F); VAL2: 63mW
R62 R69 = R: CHIPSIZE: 1608; COMP: GDM010004481; COMPONENTTYPE: 4; GCOUNT: 1; MAXGCOUNT: 1; SAVECOUNT: 0; SIZECODESMD: 1005; VAL1: 120k(F); VAL2: 63mW
R63 = R: CHIPSIZE: 1608; COMP: GDM010004481; COMPONENTTYPE: 4; GCOUNT: 1; MAXGCOUNT: 1; SAVECOUNT: 0; SIZECODESMD: 1005; VAL1: 56k(F); VAL2: 63mW
R64 R151 R201 = R: CHIPSIZE: 1608; COMP: GDM010004481; COMPONENTTYPE: 4; GCOUNT: 1; MAXGCOUNT: 1; SAVECOUNT: 0; SIZECODESMD: 1005; VAL1: 1(J); VAL2: 63mW
R66 = R: CHIPSIZE: 1608; COMP: GDM010004481; COMPONENTTYPE: 4; GCOUNT: 1; MAXGCOUNT: 1; SAVECOUNT: 0; SIZECODESMD: 1005; VAL1: 3.9k(J); VAL2: 63mW
R67 R68 R271 = R: CHIPSIZE: 1608; COMP: GDM010004481; COMPONENTTYPE: 4; GCOUNT: 1; MAXGCOUNT: 1; SAVECOUNT: 0; SIZECODESMD: 1005; VAL1: 18k(J); VAL2: 63mW
U?#5 = WAKU_DEF_A3_1: COMPONENTTYPE: 2; DATE: 2025/09/24; DESIGNED: TOSHIBA; DRAWINGNUMBER: RD244-SCHEMATIC1-01 / RD265-SCHEMATIC1-01 / RD266-SCHEMATIC1-01; FUNCTION: PFC Controller; PAGENUMBER: 2; REVISION: 01; SAVECOUNT: 3; SHEETNUMBER: 2/7; SHTSAVECOUNT: 140; TIME: 14:20:16; TITLE: 3kW Power Supply for Servers and Telecoms Using Surface-Mounted SiC MOSFET / 3kW Power Supply for AI Servers Using Surface-Mounted SiC MOSFET / 3kW Power Supply for Electric Scooter Fast Chargers Using SiC MOSFET; UPDATEDATE: 2025.9.25; UPDATETIME: 13:12:48; UPDATEUSER: t5459927
A101 A102 = RD-244_FB_UNIT: COMPONENTTYPE: 4; VAL2: 4pcs x pinsocket; VAL3: 3305-1-15-80-47-27-10-0
C151 C152 C201 C202 = C: CHIPSIZE: 3216; COMP: PRT_46; COMPONENTTYPE: 4; GCOUNT: 1; MAXGCOUNT: 1; SAVECOUNT: 0; SIZECODESMD: 3216; VAL1: 10uF(K); VAL2: 25V
C154 C204 = C: ADSCNVFLAG: ON; ADSCOMPONENTNAME: C_4532; CHIPSIZE: 1005; COMP: K0301583; COMPONENTTYPE: 4; GATENO: 1; GCOUNT: 1; ICX_PART_MODEL: CON_150N; MAXGCOUNT: 1; SAVECOUNT: 0; SIZECODESMD: 4532; SQ_PART_MODEL: CON_150N; VAL1: 330nF(K); VAL2: 250V
C155 C205 = C: ADSCNVFLAG: ON; ADSCOMPONENTNAME: C_4532; CHIPSIZE: 1005; COMP: K0301583; COMPONENTTYPE: 4; GATENO: 1; GCOUNT: 1; ICX_PART_MODEL: CON_150N; MAXGCOUNT: 1; NOTMOUNT: NOT MOUNT; SAVECOUNT: 0; SIZECODESMD: 4532; SQ_PART_MODEL: CON_150N; VAL1: 330nF(K); VAL2: 250V
C501-C503 = CP: CHIPSIZE: D10xL22; COMP: PRT_3; COMPONENTTYPE: 4; GCOUNT: 1; MAXGCOUNT: 1; SIZECODESMD: DIP; VAL1: 330uF(M); VAL2: 63V
C504 C507 C508 = GRM21BC71E106KE01: CHIPSIZE: 1005; COMPONENTTYPE: 4; GCOUNT: 1; MAXGCOUNT: 1; SIZECODESMD: 2012; VAL1: 33nF(J); VAL2: 100V
C510 C511 = GRM21BC71E106KE01: CHIPSIZE: 1005; COMPONENTTYPE: 4; GCOUNT: 1; MAXGCOUNT: 1; NOTMOUNT: NOT MOUNT; SIZECODESMD: 2012; VAL1: 33nF(J); VAL2: 100V
CN101 CN103 CN104 CN106 = LONGHOLE_2R5-5R5: COMPONENTTYPE: 4
CN102 CN105 = LONGHOLE_2R5-4R5: COMPONENTTYPE: 4
CN151 CN152 CN201 CN202 = TH_PHI_4R5: COMPONENTTYPE: 4
CN153 CN203 = LONGHOLE_4R5-8R5: COMPONENTTYPE: 4
D101 D102 = TRS8E65F: COMPONENTTYPE: 4; GCOUNT: 1; MAXGCOUNT: 1; USERCOMPTEXT3: TOSHIBA; VAL2: 650V,8A
D151 D152 D154 D155 D201 D202 D204 D205 = CUHS15S30: COMPONENTTYPE: 4; USERCOMPTEXT2: 30V,1.5A; USERCOMPTEXT3: TOSHIBA
D153 D156 D203 D206 = DMH: COMP: PRT_25; COMPONENTTYPE: 4; USERCOMPTEXT2: 30V,0.2A; USERCOMPTEXT3: TOSHIBA; VAL3: TBAT54
D157 D158 D207 D208 = D: COMP: PRT_14; COMPONENTTYPE: 4; GCOUNT: 1; MAXGCOUNT: 1; USERCOMPTEXT2: 200V,3A; USERCOMPTEXT3: TOSHIBA; VAL3: CMH01
D251 = D: COMP: PRT_27; COMPONENTTYPE: 4; GCOUNT: 1; MAXGCOUNT: 1; USERCOMPTEXT2: 80V,0.1A; USERCOMPTEXT3: TOSHIBA; VAL1: BAS316; VAL3: BAS316
IC151 IC201 = L27524: COMP: PRT_63; COMPONENTTYPE: 4; VAL3: UCC27524AD
L101 = TMSD-Y3001: COMP: 08C25178; COMPONENTTYPE: 4; VAL2: (Rated Current/Idc=0A); VAL3: 08C25178
L151 L201 = TAM-CTW32A6R5: COMPONENTTYPE: 4; GCOUNT: 1; MAXGCOUNT: 1
Q151 Q152 Q154 Q155 Q201 Q202 Q204 Q205 = TPH2R408QM_8PIN: COMP: TPW2900ENH; COMPONENTTYPE: 4; GCOUNT: 1; MAXGCOUNT: 1; USERCOMPTEXT3: TOSHIBA; VAL3: TPW2900ENH
Q153 Q156 Q203 Q206 = TPH2R408QM_8PIN: COMP: TPW2900ENH; COMPONENTTYPE: 4; GCOUNT: 1; MAXGCOUNT: 1; NOTMOUNT: MOUNT; USERCOMPTEXT3: TOSHIBA; VAL3: TPW2900ENH
R101 R102 = R: ADSCNVFLAG: ON; ADSCOMPONENTNAME: R_6332; CHIPSIZE: 6432; COMP: GDM010001640; COMPONENTTYPE: 4; GCOUNT: 1; ICX_PART_MODEL: RES_47K; MAXGCOUNT: 1; NOTMOUNT: MOUNT; SAVECOUNT: 0; SIZECODESMD: 6332; SQ_PART_MODEL: RES_47K; USERCOMPTEXT1: 300K(J); USERCOMPTEXT2: 1W; VAL1: 47k(J); VAL2: 1W
R152 R155 R202 R205 = R: CHIPSIZE: 3216; COMP: R2012; COMPONENTTYPE: 4; GCOUNT: 1; MAXGCOUNT: 1; SAVECOUNT: 0; SIZECODESMD: 2012; VAL1: 10(J); VAL2: 250mW
R153 R156 R203 R206 = R: CHIPSIZE: 3216; COMP: R2012; COMPONENTTYPE: 4; GCOUNT: 1; MAXGCOUNT: 1; SAVECOUNT: 0; SIZECODESMD: 2012; VAL1: 3(J); VAL2: 250mW
R154 R157 R204 R207 = R: CHIPSIZE: 1608; COMP: GDM010004481; COMPONENTTYPE: 4; GCOUNT: 1; MAXGCOUNT: 1; SAVECOUNT: 0; SIZECODESMD: 1005; VAL1: 10k(J); VAL2: 63mW
R158 R208 = R: ADSCOMPONENTNAME: R_3216; CHIPSIZE: 3216; COMP: PRT_5; COMPONENTTYPE: 4; GCOUNT: 1; MAXGCOUNT: 1; SAVECOUNT: 0; SIZECODESMD: 3216; VAL1: 100k(F); VAL2: 250mW
R159 R209 = R: ADSCNVFLAG: ON; COMP: CRGH2512J620R; COMPONENTTYPE: 4; GCOUNT: 1; ICX_PART_MODEL: RES_47K; MAXGCOUNT: 1; SAVECOUNT: 0; SIZECODESMD: 6432; SQ_PART_MODEL: RES_47K; USERCOMPTEXT1: 27K(J); VAL1: 47k(J); VAL2: 1W
R160 R210 = R: ADSCOMPONENTNAME: R_3216; CHIPSIZE: 3216; COMP: PRT_5; COMPONENTTYPE: 4; GCOUNT: 1; MAXGCOUNT: 1; NOTMOUNT: NOT MOUNT; SAVECOUNT: 0; SIZECODESMD: 3216; VAL1: 100k(F); VAL2: 250mW
R251 = R: ADSCNVFLAG: ON; ADSCOMPONENTNAME: R_3216; CHIPSIZE: 1608; COMP: PRT_5; COMPONENTTYPE: 4; GCOUNT: 1; ICX_PART_MODEL: RES_4.87K; MAXGCOUNT: 1; SAVECOUNT: 0; SIZECODESMD: 3216; SQ_PART_MODEL: RES_4.87K; VAL1: 330(J); VAL2: 250mW
R501 = R: ADSCNVFLAG: ON; ADSCOMPONENTNAME: R_6332; CHIPSIZE: 6432; COMP: GDM010001640; COMPONENTTYPE: 4; GCOUNT: 1; ICX_PART_MODEL: RES_47K; MAXGCOUNT: 1; SAVECOUNT: 0; SIZECODESMD: 6332; SQ_PART_MODEL: RES_47K; USERCOMPTEXT1: 10K(J); USERCOMPTEXT2: 1W; VAL1: 47k(J); VAL2: 1W
R502 R503 = R: ADSCNVFLAG: ON; ADSCOMPONENTNAME: R_6332; CHIPSIZE: 6432; COMP: GDM010001640; COMPONENTTYPE: 4; GCOUNT: 1; ICX_PART_MODEL: RES_47K; MAXGCOUNT: 1; NOTMOUNT: NOT MOUNT; SAVECOUNT: 0; SIZECODESMD: 6332; SQ_PART_MODEL: RES_47K; USERCOMPTEXT1: 10K(J); USERCOMPTEXT2: 1W; VAL1: 47k(J); VAL2: 1W
T101 = T2AA: COMP: PRT_65; COMPONENTTYPE: 4; GCOUNT: 1; MAXGCOUNT: 1; VAL1: 1:100; VAL3: PE-63587
T151 T201 = TAM-PQ40-20-3: COMP: TAM-PQ40-16-3; COMPONENTTYPE: 4; SAVECOUNT: 21; USERCOMPTEXT1: 16:3:3; VAL3: TAM-PQ40-16-3
U?#4 = WAKU_DEF_A3_1: COMPONENTTYPE: 2; DATE: 2025/09/24; DESIGNED: TOSHIBA; DRAWINGNUMBER: RD244-SCHEMATIC1-01 / RD265-SCHEMATIC1-01 / RD266-SCHEMATIC1-01; FUNCTION: PSFB Synchronous Rectification; PAGENUMBER: 3; REVISION: 01; SAVECOUNT: 3; SHEETNUMBER: 3/7; SHTSAVECOUNT: 272; TIME: 12:01:09; TITLE: 3kW Power Supply for Servers and Telecoms Using Surface-Mounted SiC MOSFET / 3kW Power Supply for AI Servers Using Surface-Mounted SiC MOSFET / 3kW Power Supply for Electric Scooter Fast Chargers Using SiC MOSFET; UPDATEDATE: 2025.9.25; UPDATETIME: 13:12:48; UPDATEUSER: t5459927
C251 = GRM21BC71E106KE01: CHIPSIZE: 1005; COMPONENTTYPE: 4; GCOUNT: 1; MAXGCOUNT: 1; SIZECODESMD: 2012; VAL1: 2.2uF(K)
C256 = C: ADSCNVFLAG: ON; ADSCOMPONENTNAME: C_1005; CHIPSIZE: 1005; COMP: PRT_52; COMPONENTTYPE: 4; GCOUNT: 1; ICX_PART_MODEL: CON_5.6N; MAXGCOUNT: 1; SAVECOUNT: 0; SIZECODESMD: 1005; SQ_PART_MODEL: CON_5.6N; VAL1: 3.3nF(K); VAL2: 50V
C257 = C: ADSCNVFLAG: ON; ADSCOMPONENTNAME: C_1005; CHIPSIZE: 1005; COMP: PRT_52; COMPONENTTYPE: 4; GCOUNT: 1; ICX_PART_MODEL: CON_560P; MAXGCOUNT: 1; SAVECOUNT: 0; SIZECODESMD: 1005; SQ_PART_MODEL: CON_560P; VAL1: 330pF(J); VAL2: 50V
C258 = C: CHIPSIZE: 3216; COMP: PRT_46; COMPONENTTYPE: 4; GCOUNT: 1; MAXGCOUNT: 1; NOTMOUNT: NOT MOUNT; SAVECOUNT: 0; SIZECODESMD: 3216; VAL1: 10uF(K); VAL2: 25V
DP258 = TP: COMP: PRT_34; COMPONENTTYPE: 4; VAL3: LC-22-S-BLACK
IC251 = L28950: COMP: PRT_16; COMPONENTTYPE: 4; VAL3: UCC28951
R252 = R: CHIPSIZE: 1608; COMP: GDM010004481; COMPONENTTYPE: 4; GCOUNT: 1; MAXGCOUNT: 1; SAVECOUNT: 0; SIZECODESMD: 1005; VAL1: 13k(F); VAL2: 63mW
R253 = R: CHIPSIZE: 1608; COMP: GDM010004481; COMPONENTTYPE: 4; GCOUNT: 1; MAXGCOUNT: 1; SAVECOUNT: 0; SIZECODESMD: 1005; VAL1: 15k(F); VAL2: 63mW
R254 = R: CHIPSIZE: 1608; COMP: GDM010004481; COMPONENTTYPE: 4; GCOUNT: 1; MAXGCOUNT: 1; SAVECOUNT: 0; SIZECODESMD: 1005; VAL1: 90k(J); VAL2: 63mW
R255 = R: ADSCNVFLAG: ON; ADSCOMPONENTNAME: R_1608; CHIPSIZE: 1608; COMP: GDM010004481; COMPONENTTYPE: 4; GCOUNT: 1; ICX_PART_MODEL: RES_15K; MAXGCOUNT: 1; SAVECOUNT: 0; SIZECODESMD: 1005; SQ_PART_MODEL: RES_15K; VAL1: 18k(F); VAL2: 63mW
R256 = R: CHIPSIZE: 1608; COMP: GDM010004481; COMPONENTTYPE: 4; GCOUNT: 1; MAXGCOUNT: 1; SAVECOUNT: 0; SIZECODESMD: 1005; VAL1: 22(J); VAL2: 63mW
R259 = R: CHIPSIZE: 1608; COMP: GDM010004481; COMPONENTTYPE: 4; GCOUNT: 1; MAXGCOUNT: 1; SAVECOUNT: 0; SIZECODESMD: 1005; VAL1: 12k(F); VAL2: 63mW
R260 = R: ADSCOMPONENTNAME: R_1005; CHIPSIZE: 1608; COMP: GDM010004481; COMPONENTTYPE: 4; GCOUNT: 1; MAXGCOUNT: 1; SAVECOUNT: 0; SIZECODESMD: 1005; VAL1: 220(J); VAL2: 63mW
R261 R264 = R: CHIPSIZE: 1608; COMP: GDM010004481; COMPONENTTYPE: 4; GCOUNT: 1; MAXGCOUNT: 1; SAVECOUNT: 0; SIZECODESMD: 1005; VAL1: 6.8k(J); VAL2: 63mW
R262 R263 = R: ADSCOMPONENTNAME: R_1005; CHIPSIZE: 1608; COMP: GDM010004481; COMPONENTTYPE: 4; GCOUNT: 1; MAXGCOUNT: 1; NOTMOUNT: NOT MOUNT; SAVECOUNT: 0; SIZECODESMD: 1005; VAL1: 6.8k(J); VAL2: 63mW
R265 = R: ADSCOMPONENTNAME: R_1005; CHIPSIZE: 1608; COMP: GDM010004481; COMPONENTTYPE: 4; GCOUNT: 1; MAXGCOUNT: 1; SAVECOUNT: 0; SIZECODESMD: 1005; VAL1: 6.8k(J); VAL2: 63mW
R266 R267 = R: CHIPSIZE: 1608; COMP: GDM010004481; COMPONENTTYPE: 4; GCOUNT: 1; MAXGCOUNT: 1; SAVECOUNT: 0; SIZECODESMD: 1005; VAL1: 2.2k(F); VAL2: 63mW
R268 = R: ADSCNVFLAG: ON; ADSCOMPONENTNAME: R_1608; CHIPSIZE: 1608; COMP: GDM010004481; COMPONENTTYPE: 4; GCOUNT: 1; ICX_PART_MODEL: RES_0; MAXGCOUNT: 1; SAVECOUNT: 0; SIZECODESMD: 1005; SQ_PART_MODEL: RES_0; VAL1: 0; VAL2: 63mW
R269 R277 = R: CHIPSIZE: 1608; COMP: GDM010004481; COMPONENTTYPE: 4; GCOUNT: 1; MAXGCOUNT: 1; NOTMOUNT: NOT MOUNT; SAVECOUNT: 0; SIZECODESMD: 1005; VAL1: 0; VAL2: 63mW
R270 R312 R505 R506 = R: CHIPSIZE: 1608; COMP: GDM010004481; COMPONENTTYPE: 4; GCOUNT: 1; MAXGCOUNT: 1; SAVECOUNT: 0; SIZECODESMD: 1005; VAL1: 0; VAL2: 63mW
R272 = R: CHIPSIZE: 1608; COMP: GDM010004481; COMPONENTTYPE: 4; GCOUNT: 1; MAXGCOUNT: 1; SAVECOUNT: 0; SIZECODESMD: 1005; VAL1: 430(J); VAL2: 63mW
R273 = R: CHIPSIZE: 1608; COMP: GDM010004481; COMPONENTTYPE: 4; GCOUNT: 1; MAXGCOUNT: 1; SAVECOUNT: 0; SIZECODESMD: 1005; VAL1: 680(J); VAL2: 63mW
R274-R276 = R: CHIPSIZE: 3216; COMP: PRT_5; COMPONENTTYPE: 4; GCOUNT: 1; MAXGCOUNT: 1; SAVECOUNT: 0; SIZECODESMD: 3216; VAL1: 33(J); VAL2: 250mW
R278 = R: CHIPSIZE: 1608; COMP: GDM010004481; COMPONENTTYPE: 4; GCOUNT: 1; MAXGCOUNT: 1; SAVECOUNT: 0; SIZECODESMD: 1005; VAL1: 36k(F); VAL2: 63mW
R279 = R: CHIPSIZE: 1608; COMP: GDM010004481; COMPONENTTYPE: 4; GCOUNT: 1; MAXGCOUNT: 1; SAVECOUNT: 0; SIZECODESMD: 1005; VAL1: 6.8k(D); VAL2: 63mW
R282 = R: CHIPSIZE: 1608; COMP: GDM010004481; COMPONENTTYPE: 4; GCOUNT: 1; MAXGCOUNT: 1; SAVECOUNT: 0; SIZECODESMD: 1005; VAL1: 2.2k(D); VAL2: 63mW
R283 = R: CHIPSIZE: 1608; COMP: GDM010004481; COMPONENTTYPE: 4; GCOUNT: 1; MAXGCOUNT: 1; SAVECOUNT: 0; SIZECODESMD: 1005; VAL1: 470(D); VAL2: 63mW
R284 = R: CHIPSIZE: 3216; COMP: PRT_5; COMPONENTTYPE: 4; GCOUNT: 1; MAXGCOUNT: 1; NOTMOUNT: NOT MOUNT; SAVECOUNT: 0; SIZECODESMD: 3216; VAL1: 36(J); VAL2: 250mW
U?#3 = WAKU_DEF_A3_1: COMPONENTTYPE: 2; DATE: 2025/09/24; DESIGNED: TOSHIBA; DRAWINGNUMBER: RD244-SCHEMATIC1-01 / RD265-SCHEMATIC1-01 / RD266-SCHEMATIC1-01; FUNCTION: PSFB Controller; PAGENUMBER: 4; REVISION: 01; SAVECOUNT: 3; SHEETNUMBER: 4/7; SHTSAVECOUNT: 142; TIME: 16:14:05; TITLE: 3kW Power Supply for Servers and Telecoms Using Surface-Mounted SiC MOSFET / 3kW Power Supply for AI Servers Using Surface-Mounted SiC MOSFET / 3kW Power Supply for Electric Scooter Fast Chargers Using SiC MOSFET; UPDATEDATE: 2025.9.25; UPDATETIME: 13:12:48; UPDATEUSER: t5459927
C505 C506 = GRM21BC71E106KE01: CHIPSIZE: 1005; COMPONENTTYPE: 4; GCOUNT: 1; MAXGCOUNT: 1; SIZECODESMD: 2012; VAL1: 1uF(K); VAL2: 100V
CN501 = C4A: ADSCNVFLAG: ON; CDBNAME: K22S0019; COMP: K22S0019; COMPONENTNAME: K22S0019_package; COMPONENTTYPE: 4; FUNCN: K22S0019; GCOUNT: 1; MAXGCOUNT: 1; USERCOMPTEXT3: [JCY; VAL3: B4B-XH-A
CN502 = C2A: ADSCNVFLAG: ON; CDBNAME: K2203993; COMP: K2203993; COMPONENTNAME: K2203993_package; COMPONENTTYPE: 4; FUNCN: K2203993; GCOUNT: 1; MAXGCOUNT: 1; OUMEPARTTYPE2: CN; USERCOMPTEXT3: [JCY; VAL3: B2B-XH-A(LF)(SN)
IC501 = LM74700-Q1: COMPONENTTYPE: 4
Q501-Q504 Q506 Q507 = NCHMOSFET_SOPADVANCE-E-01: COMPONENTTYPE: 4; GCOUNT: 1; MAXGCOUNT: 1; SAVECOUNT: 30; UPDATEDATE: 2024/5/27; USERCOMPTEXT3: TOSHIBA; VAL1: 80V; VAL2: **A; VAL3: TPM1R908QM
R504 = R: CHIPSIZE: 1608; COMP: R2012; COMPONENTTYPE: 4; GCOUNT: 1; MAXGCOUNT: 1; SAVECOUNT: 0; SIZECODESMD: 2012; VAL1: 3(J); VAL2: 250mW
TB501 TB502 = 7460305: ADSCNVFLAG: ON; COMPONENTTYPE: 4; GCOUNT: 1; MAXGCOUNT: 1; USERCOMPTEXT1: Wurth
U?#2 = WAKU_DEF_A3_1: COMPONENTTYPE: 2; DATE: 2025/09/24; DESIGNED: TOSHIBA; DRAWINGNUMBER: RD244-SCHEMATIC1-01 / RD265-SCHEMATIC1-01 / RD266-SCHEMATIC1-01; FUNCTION: ORing & 50V Output; PAGENUMBER: 5; REVISION: 01; SAVECOUNT: 3; SHEETNUMBER: 5/7; SHTSAVECOUNT: 121; TIME: 12:01:09; TITLE: 3kW Power Supply for Servers and Telecoms Using Surface-Mounted SiC MOSFET / 3kW Power Supply for AI Servers Using Surface-Mounted SiC MOSFET / 3kW Power Supply for Electric Scooter Fast Chargers Using SiC MOSFET; UPDATEDATE: 2025.9.25; UPDATETIME: 13:12:48; UPDATEUSER: t5459927
C301 = C: CHIPSIZE: 3216; COMP: PRT_46; COMPONENTTYPE: 4; GCOUNT: 1; MAXGCOUNT: 1; SAVECOUNT: 0; SIZECODESMD: 3216; VAL1: 47nF(K); VAL2: 630V
C304 = C: CHIPSIZE: 1005; COMP: PRT_52; COMPONENTTYPE: 4; GCOUNT: 1; MAXGCOUNT: 1; SAVECOUNT: 0; SIZECODESMD: 1005; VAL1: 47nF(K); VAL2: 50V
C307 = C: CHIPSIZE: 1005; COMP: PRT_52; COMPONENTTYPE: 4; GCOUNT: 1; MAXGCOUNT: 1; SAVECOUNT: 0; SIZECODESMD: 1005; VAL1: 470nF(M); VAL2: 50V
C308 = C: CHIPSIZE: 1005; COMP: PRT_52; COMPONENTTYPE: 4; GCOUNT: 1; MAXGCOUNT: 1; NOTMOUNT: NOT MOUNT; SAVECOUNT: 0; SIZECODESMD: 1005; VAL1: 10nF(K); VAL2: 50V
D302 = ZENERDIODE_USC-01: ADSCNVFLAG: ON; ADSCOMPONENTNAME: D_ZD; COMPONENTTYPE: 4; GCOUNT: 1; MAXGCOUNT: 1; VAL1: 5.6V; VAL3: XCUZ5V6
D303 = D: COMP: PRT_27; COMPONENTTYPE: 4; USERCOMPTEXT2: 80V,0.1A; USERCOMPTEXT3: TOSHIBA; VAL1: 1SS352(TPH3,F); VAL3: 1SS352
D304 = 1SS405: ADSCNVFLAG: ON; ADSCOMPONENTNAME: D_SBD; COMPONENTTYPE: 4; GCOUNT: 1; MAXGCOUNT: 1; SIZECODESMD: SOD-523; USERCOMPTEXT3: TOSHIBA
DS301 = TLP385: ADSCNVFLAG: ON; COMPONENTTYPE: 4; GATENO: 1; GCOUNT: 1; MAXGCOUNT: 1; USERCOMPTEXT3: TOSHIBA
IC301 IC302 = L7704: ADSCNVFLAG: ON; COMP: GDM470001845; COMPONENTTYPE: 4; FUNCTION: OTHER; GCOUNT: 1; MAXGCOUNT: 1; VAL1: NJU7704F3-25A(TE1); VAL3: NJU7704F3-42A(TE1)
IC303 = DCL540C01: COMPONENTTYPE: 4; FUNCTION: FXD; GCOUNT: 1; MAXGCOUNT: 1; USERCOMPTEXT3: TOSHIBA
Q301 Q351 = MFNN: ADSCNVFLAG: ON; ADSCOMPONENTNAME: Q_MFNN; COMP: GDM410000663; COMPONENTTYPE: 4; GCOUNT: 1; MAXGCOUNT: 1; USERCOMPTEXT3: TOSHIBA; VAL1: SSM3K15AMFV,L3F(T; VAL3: SSM3K15AMFV
R301-R304 R309-R311 = R: CHIPSIZE: 1608; COMP: PRT_5; COMPONENTTYPE: 4; GCOUNT: 1; MAXGCOUNT: 1; SAVECOUNT: 0; SIZECODESMD: 3216; VAL1: 1M(J); VAL2: 250mW
R305 = R: CHIPSIZE: 1608; COMP: GDM010004481; COMPONENTTYPE: 4; GCOUNT: 1; MAXGCOUNT: 1; SAVECOUNT: 0; SIZECODESMD: 1005; VAL1: 82k(J); VAL2: 63mW
R306 = R: CHIPSIZE: 1608; COMP: GDM010004481; COMPONENTTYPE: 4; GCOUNT: 1; MAXGCOUNT: 1; SAVECOUNT: 0; SIZECODESMD: 1005; VAL1: 12k(J); VAL2: 63mW
R307 = R: CHIPSIZE: 1608; COMP: GDM010004481; COMPONENTTYPE: 4; GCOUNT: 1; MAXGCOUNT: 1; SAVECOUNT: 0; SIZECODESMD: 1005; VAL1: 680k(F); VAL2: 63mW
R308 R353 = R: CHIPSIZE: 1608; COMP: GDM010004481; COMPONENTTYPE: 4; GCOUNT: 1; MAXGCOUNT: 1; SAVECOUNT: 0; SIZECODESMD: 1005; VAL1: 10(J); VAL2: 63mW
R314 R315 R351 R352 = R: CHIPSIZE: 1608; COMP: GDM010004481; COMPONENTTYPE: 4; GCOUNT: 1; MAXGCOUNT: 1; SAVECOUNT: 0; SIZECODESMD: 1005; VAL1: 22k(J); VAL2: 63mW
R316 = R: ADSCNVFLAG: ON; ADSCOMPONENTNAME: R_3216; CHIPSIZE: 1608; COMP: PRT_5; COMPONENTTYPE: 4; GCOUNT: 1; ICX_PART_MODEL: RES_4.87K; MAXGCOUNT: 1; SAVECOUNT: 0; SIZECODESMD: 3216; SQ_PART_MODEL: RES_4.87K; VAL1: 3.3k(J); VAL2: 250mW
R317 = R: CHIPSIZE: 1608; COMP: GDM010004481; COMPONENTTYPE: 4; GCOUNT: 1; MAXGCOUNT: 1; SAVECOUNT: 0; SIZECODESMD: 1005; VAL1: 1.2k(J); VAL2: 63mW
R355 R358 R361 R364 = R: CHIPSIZE: 1608; COMP: GDM010004481; COMPONENTTYPE: 4; GCOUNT: 1; MAXGCOUNT: 1; SAVECOUNT: 0; SIZECODESMD: 1005; VAL1: 4.7k(J); VAL2: 63mW
R356 R359 R362 R365 = R: CHIPSIZE: 1608; COMP: GDM010004481; COMPONENTTYPE: 4; GCOUNT: 1; MAXGCOUNT: 1; SAVECOUNT: 0; SIZECODESMD: 1005; VAL1: 2.2k(J); VAL2: 63mW
U?#1 = WAKU_DEF_A3_1: COMPONENTTYPE: 2; DATE: 2025/09/24; DESIGNED: TOSHIBA; DRAWINGNUMBER: RD244-SCHEMATIC1-01 / RD265-SCHEMATIC1-01 / RD266-SCHEMATIC1-01; FUNCTION: Isolator & Detection Circuit; PAGENUMBER: 6; REVISION: 01; SAVECOUNT: 3; SHEETNUMBER: 6/7; SHTSAVECOUNT: 262; TIME: 16:14:05; TITLE: 3kW Power Supply for Servers and Telecoms Using Surface-Mounted SiC MOSFET / 3kW Power Supply for AI Servers Using Surface-Mounted SiC MOSFET / 3kW Power Supply for Electric Scooter Fast Chargers Using SiC MOSFET; UPDATEDATE: 2025.9.25; UPDATETIME: 13:12:48; UPDATEUSER: t5459927
C401 = CP: COMP: PRT_3; COMPONENTTYPE: 4; SIZECODESMD: DIP; VAL1: 6.8uF(M); VAL2: 450V
C402 C403 = C: COMP: PRT_46; COMPONENTTYPE: 4; SAVECOUNT: 0; SIZECODESMD: 3216; VAL1: 22nF(K); VAL2: 630V
C405 C406 = C: COMP: PRT_52; COMPONENTTYPE: 4; NOTMOUNT: NOT MOUNT; SAVECOUNT: 0; SIZECODESMD: 1005; VAL1: 150pF(J); VAL2: 50V
C407 = C: COMP: PRT_52; COMPONENTTYPE: 4; SAVECOUNT: 0; SIZECODESMD: 1005; VAL1: 470pF(J); VAL2: 50V
C408 = EMLA350ARA331MJA0G: COMPONENTTYPE: 4; GCOUNT: 1; MAXGCOUNT: 1; SIZECODESMD: 1010
C409 = C: COMP: PRT_52; COMPONENTTYPE: 4; NOTMOUNT: NOT MOUNT; SAVECOUNT: 0; SIZECODESMD: 1005; VAL1: 2.2nF(K); VAL2: 50V
C410 = C: COMP: PRT_52; COMPONENTTYPE: 4; SAVECOUNT: 0; SIZECODESMD: 1005; VAL1: 1nF(K); VAL2: 50V
C411-C413 C452 C453 = C: ADSCNVFLAG: ON; ADSCOMPONENTNAME: C_1608; CHIPSIZE: 1005; COMP: PRT_52; COMPONENTTYPE: 4; GCOUNT: 1; ICX_PART_MODEL: CON_1U; MAXGCOUNT: 1; SAVECOUNT: 0; SIZECODESMD: 1005; SQ_PART_MODEL: CON_1U; VAL1: 1uF(M); VAL2: 25V
C414 = DE2B3SA221KA3BT02F: COMPONENTTYPE: 4; GCOUNT: 1; MAXGCOUNT: 1; SIZECODESMD: DIP; USERCOMPTEXT1: 470pF(K)
C451 = CP: COMP: PRT_3; COMPONENTTYPE: 4; SIZECODESMD: DIP; VAL1: 1200uF(M); VAL2: 25V
D401 = CRF03A: COMPONENTTYPE: 4; GCOUNT: 1; MAXGCOUNT: 1; USERCOMPTEXT2: 600V,0.7A; USERCOMPTEXT3: TOSHIBA
D402 D403 = D: ADSCNVFLAG: ON; ADSCOMPONENTNAME: D_D; COMP: GDM420000387; COMPONENTTYPE: 4; GATENO: 1; GCOUNT: 1; MAXGCOUNT: 1; USERCOMPTEXT2: 200V,1A; USERCOMPTEXT3: TOSHIBA; VAL1: CRH01; VAL3: CRH01
D404 = SBD: ADSCNVFLAG: ON; ADSCOMPONENTNAME: D_SBD; COMP: K4200730; COMPONENTTYPE: 4; GCOUNT: 1; MAXGCOUNT: 1; USERCOMPTEXT2: 30V,1A; USERCOMPTEXT3: TOSHIBA; VAL1: CRS01; VAL3: CRS01
D405 = D: COMP: PRT_26; COMPONENTTYPE: 4; GCOUNT: 1; MAXGCOUNT: 1; NOTMOUNT: NOT MOUNT; USERCOMPTEXT2: 100V,0.25A; USERCOMPTEXT3: TOSHIBA; VAL3: BAS316
D451 = RF501BGE2S: COMPONENTTYPE: 4
F401 = F: COMP: 808****0440_LF; COMPONENTTYPE: 4; SAVECOUNT: 0; VAL1: 2A; VAL3: 80812000440
IC401 = UCC28711DR: COMPONENTTYPE: 4
IC402 = LM317MDCY: COMPONENTTYPE: 4; FUNCTION: FXD; GCOUNT: 1; MAXGCOUNT: 1
IC403 IC451 = TCR1HF50B: COMPONENTTYPE: 4; SAVECOUNT: 17; UPDATEDATE: 2023/4/18; USERCOMPTEXT3: TOSHIBA
Q401 = MFNF: COMP: K4100860; COMPONENTTYPE: 4; USERCOMPTEXT3: TOSHIBA; VAL3: TK12A80W
R401 = R: COMP: PRT_54; COMPONENTTYPE: 4; SAVECOUNT: 0; SIZECODESMD: TH; VAL1: 27k(J); VAL2: 3W
R402 = R: COMP: R2012; COMPONENTTYPE: 4; SAVECOUNT: 0; SIZECODESMD: 2012; VAL1: 10(J); VAL2: 250mW
R403 = R: COMP: GDM010004481; COMPONENTTYPE: 4; GCOUNT: 1; MAXGCOUNT: 1; SAVECOUNT: 0; SIZECODESMD: 1005; VAL1: 10k(J); VAL2: 63mW
R404-R406 = R: COMP: PRT_5; COMPONENTTYPE: 4; SAVECOUNT: 0; SIZECODESMD: 3216; VAL1: 1.2(F); VAL2: 250mW
R407 = R: COMP: GDM010004481; COMPONENTTYPE: 4; GCOUNT: 1; MAXGCOUNT: 1; SAVECOUNT: 0; SIZECODESMD: 1005; VAL1: 100k(J); VAL2: 63mW
R408 = R: COMP: GDM010004481; COMPONENTTYPE: 4; GCOUNT: 1; MAXGCOUNT: 1; SAVECOUNT: 0; SIZECODESMD: 1005; VAL1: 22(J); VAL2: 63mW
R409 = R: COMP: GDM010004481; COMPONENTTYPE: 4; SAVECOUNT: 0; SIZECODESMD: 1005; VAL1: 3.3k(J); VAL2: 63mW
R410 = R: COMP: GDM010004481; COMPONENTTYPE: 4; GCOUNT: 1; MAXGCOUNT: 1; SAVECOUNT: 0; SIZECODESMD: 1005; VAL1: 100k(F); VAL2: 63mW
R411 = R: COMP: GDM010004481; COMPONENTTYPE: 4; GCOUNT: 1; MAXGCOUNT: 1; SAVECOUNT: 0; SIZECODESMD: 1005; VAL1: 22k(F); VAL2: 63mW
R412 = R: COMP: GDM010004481; COMPONENTTYPE: 4; GCOUNT: 1; MAXGCOUNT: 1; SAVECOUNT: 0; SIZECODESMD: 1005; VAL1: 33(J); VAL2: 63mW
R413 = R: COMP: GDM010004481; COMPONENTTYPE: 4; GCOUNT: 1; MAXGCOUNT: 1; SAVECOUNT: 0; SIZECODESMD: 1005; VAL1: 6.2k(D); VAL2: 63mW
R414 = R: COMP: GDM010004481; COMPONENTTYPE: 4; GCOUNT: 1; MAXGCOUNT: 1; SAVECOUNT: 0; SIZECODESMD: 1005; VAL1: 470(D); VAL2: 63mW
R415 R453 = R: CHIPSIZE: 1608; COMP: GDM010004481; COMPONENTTYPE: 4; GCOUNT: 1; MAXGCOUNT: 1; SAVECOUNT: 0; SIZECODESMD: 1005; VAL1: 100(J); VAL2: 63mW
R416 = R: ADSCNVFLAG: ON; ADSCOMPONENTNAME: R_1005; CHIPSIZE: 1608; COMP: GDM010004481; COMPONENTTYPE: 4; GCOUNT: 1; ICX_PART_MODEL: RES_0; MAXGCOUNT: 1; SAVECOUNT: 0; SIZECODESMD: 1005; SQ_PART_MODEL: RES_0; VAL1: 1(J); VAL2: 63mW
R417 = R: COMP: GDM010004481; COMPONENTTYPE: 4; GCOUNT: 1; MAXGCOUNT: 1; SAVECOUNT: 0; SIZECODESMD: 1005; VAL1: 2.2k(F); VAL2: 63mW
R451 = R: COMP: PRT_5; COMPONENTTYPE: 4; SAVECOUNT: 0; SIZECODESMD: 3216; VAL1: 1.2k(J); VAL2: 250mW
R452 = R: COMP: PRT_5; COMPONENTTYPE: 4; SAVECOUNT: 0; SIZECODESMD: 3216; USERCOMPTEXT1: 10m(F); VAL1: 10m(F); VAL2: 1W
R454 = R: ADSCNVFLAG: ON; ADSCOMPONENTNAME: R_1005; CHIPSIZE: 1608; COMP: GDM010004481; COMPONENTTYPE: 4; GCOUNT: 1; ICX_PART_MODEL: RES_0; MAXGCOUNT: 1; SAVECOUNT: 0; SIZECODESMD: 1005; SQ_PART_MODEL: RES_0; VAL1: 0; VAL2: 63mW
T401 = TAM-PQ20-36-5: COMPONENTTYPE: 4; SAVECOUNT: 21
U?#7 = WAKU_DEF_A3_1: COMPONENTTYPE: 2; DATE: 2025/09/24; DRAWINGNUMBER: RD244-SCHEMATIC1-01 / RD265-SCHEMATIC1-01 / RD266-SCHEMATIC1-01; FUNCTION: Auxiliary Power; NOTMOUNT: MOUNT; PAGENUMBER: 7; REVISION: 01; SAVECOUNT: 20; SHEETNUMBER: 7/7; SHTSAVECOUNT: 218; TIME: 18:12:27; TITLE: 3kW Power Supply for Servers and Telecoms Using Surface-Mounted SiC MOSFET / 3kW Power Supply for AI Servers Using Surface-Mounted SiC MOSFET / 3kW Power Supply for Electric Scooter Fast Chargers Using SiC MOSFET; UPDATEDATE: 2025.9.25; UPDATETIME: 13:12:48; UPDATEUSER: t5459927

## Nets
P50V: C506.2 C507.2 C508.2 CN502.1 DP503.1 IC501.4 Q501.5 Q501.6 Q501.7 Q501.8 Q502.5 Q502.6 Q502.7 Q502.8 Q503.5 Q503.6 Q503.7 Q503.8 Q504.5 Q504.6 Q504.7 Q504.8 Q506.5 Q506.6 Q506.7 Q506.8 Q507.5 Q507.6 Q507.7 Q507.8 TB501.1 TB501.2 TB501.3 TB501.4 TB501.5 TB501.6 TB501.7 TB501.8
VCC5R0_1: C309.2 C413.2 IC303.16 IC403.5
VCC5R0_2: C351.2 IC303.1 R454.2
VCC12R0_2: CN501.1 CN501.2 DP451.1 DS301.6 R151.1 R201.1 R256.1 R452.2 R453.1
VCC18R0_1: A51.3(B2) A101.3 A102.3 D1.C DP404.1 R64.1 R314.2 R316.2 R415.1 R416.1
$BN000001: R73.1 R74.2
$BN000002: R56.1 R57.2
AC-L: C9.2 D51.A D53.A D55.2 L51.1 R4.2 RY1.3 RY1.6
AC-N: C8.2 C9.1 D52.A D54.A D55.3 L2.4 L52.1
ACIN: C301.2 D51.C D52.C R301.2
CS: D251.C R273.2 R274.2 R275.2 R276.2
FG: C2.1 C3.1 C4.1 C5.1 C7.1 C8.1 C54.2 C507.1 C509.2 R505.1 R506.1 TB1.3
LGND: C151.1 C152.1 C153.1 C154.1 C155.1 C201.1 C202.1 C203.1 C204.1 C205.1 C251.1 C252.1 C253.1 C254.1 C255.1 C351.1 C414.2 C451.1 C452.1 C453.1 C501.1 C502.1 C503.1 C504.1 C506.1 C508.1 C509.1 C510.1 C511.1 CN501.3 CN501.4 CN502.2 D153.A D156.A D203.A D206.A DP153.1 DP156.1 DP203.1 DP206.1 DP258.1 IC151.3 IC201.3 IC251.24 IC303.2 IC303.8 IC451.2 IC501.2 Q151.1 Q151.2 Q151.3 Q152.1 Q152.2 Q152.3 Q153.1 Q153.2 Q153.3 Q154.1 Q154.2 Q154.3 Q155.1 Q155.2 Q155.3 Q156.1 Q156.2 Q156.3 Q201.1 Q201.2 Q201.3 Q202.1 Q202.2 Q202.3 Q203.1 Q203.2 Q203.3 Q204.1 Q204.2 Q204.3 Q205.1 Q205.2 Q205.3 Q206.1 Q206.2 Q206.3 Q351.S R154.1 R157.1 R158.1 R160.1 R204.1 R207.1 R208.1 R210.1 R251.1 R252.1 R253.1 R254.1 R255.1 R257.1 R261.1 R264.1 R267.1 R272.1 R274.1 R275.1 R276.1 R277.1 R283.1 R352.1 R356.1 R359.1 R362.1 R365.1 R451.1 R501.1 R502.1 R503.1 R505.2 R506.2 T101.3 T401.8 T401.9 TB502.1 TB502.2 TB502.3 TB502.4 TB502.5 TB502.6 TB502.7 TB502.8
OUTA1: A101.1 IC303.14
OUTA2: DP252.1 IC251.22 R355.2
OUTB1: A101.2 IC303.13
OUTB2: DP253.1 IC251.21 R358.2
OUTC1: A102.1 IC303.12
OUTC2: DP254.1 IC251.20 R361.2
OUTD1: A102.2 IC303.11
OUTD2: DP255.1 IC251.19 R364.2
OUTE: DP256.1 IC151.2 IC201.2 IC251.18
OUTF: DP257.1 IC151.4 IC201.4 IC251.17
PFC_OFF: C59.2 DP51.1 IC51.18 R308.1
PFC_OUT: A51.P1(PFCOUT) C51.2 C52.2 C53.2 D55.1 DP56.1 F401.1 R70.2 R101.2 R309.2 T101.2
PN: A51.4(A2) A51.P4(PN) A101.4 A101.P3(PN) A102.4 A102.P3(PN) C11.1 C51.1 C52.1 C53.1 C54.1 C55.1 C56.1 C57.1 C58.1 C59.1 C60.1 C61.1 C62.1 C63.1 C64.1 C66.1 C68.1 C70.1 C301.1 C302.1 C303.1 C304.1 C305.1 C306.1 C307.1 C308.1 C309.1 C310.1 C401.1 C404.1 C405.1 C406.1 C407.1 C408.1 C409.1 C410.1 C411.1 C412.1 C413.1 C414.1 D2.A D55.4 D56.A D102.A D302.A DP55.1 DP303.1 DP306.1 IC51.16 IC301.2 IC302.2 IC303.9 IC303.15 IC401.4 IC403.2 Q301.S R57.1 R58.1 R60.1 R61.1 R62.1 R63.1 R66.1 R67.1 R68.1 R69.1 R74.1 R102.1 R306.1 R313.1 R315.1 R317.1 R404.1 R405.1 R406.1 R407.1 R413.1 R417.1 RY1.1 T401.4
PSFB_OUT: C501.2 C502.2 C503.2 C504.2 C505.2 C510.2 C511.2 DP502.1 IC501.3 IC501.6 L151.F L201.F Q501.1 Q501.2 Q501.3 Q502.1 Q502.2 Q502.3 Q503.1 Q503.2 Q503.3 Q504.1 Q504.2 Q504.3 Q506.1 Q506.2 Q506.3 Q507.1 Q507.2 Q507.3 R159.2 R209.2 R279.2 R501.2 R502.2 R503.2
SIG1: C1.2 C2.2 FH2.1 FH2.2 L1.2 R1.2 RV1.1
SIG2: C1.1 C3.2 CN1.1 L1.3 R2.1 RV1.2 TB1.2
SIG9: IC1.2 IC1.3 R1.1
SIG10: IC1.6 IC1.7 R2.2
SIG0012: C11.2 D1.A D2.C RY1.8
SIG0013: R3.2 R4.1
SIG0026: R71.1 R72.2
SIG0027: R70.1 R71.2
SIG0028: C64.2 C65.2 IC51.11
SIG0029: C65.1 R67.2
SIG62: C57.2 DP54.1 IC51.5 R55.1 R56.2
SIG122: C505.1 IC501.1
SIG136: IC501.5 R504.1
SIG141: DP501.1 Q501.4 Q502.4 Q503.4 Q504.4 Q506.4 Q507.4 R504.2
SIG193: CN1.3 FH1.1 FH1.2 TB1.1
SIG199: C4.2 C6.2 L1.1 L2.2
SIG200: C5.2 C6.1 L1.4 L2.3
SIG00210: C66.2 C67.2 IC51.12
SIG00211: C67.1 R68.2
SIG00212: C68.2 C69.2 IC51.3
SIG00213: C69.1 R69.2
SIG00214: IC51.19 R63.2
SIG00215: IC51.2 R58.2
SIG00216: R53.1 R54.2
SIG00217: R54.1 R55.2
SIG00218: C58.2 IC51.1
SIG00219: IC51.20 R59.2
SIG00220: IC51.6 R61.2
SIG00221: IC51.7 R62.2
SIG00222: C70.2 DP57.1 IC51.4 R72.1 R73.2
SIG00223: C63.2 IC51.13 R65.2
SIG00224: R59.1 R60.2
SIG00225: C62.2 IC51.10 R65.1 R66.2
SIG00226: C56.2 IC51.8 R52.2
SIG00227: C55.2 IC51.9 R51.2
SIG00228: C60.2 C61.2 D56.C IC51.15 R64.2
SIG00229: A51.P3(VIN_B) L52.2
SIG00230: A51.P2(VIN_A) L51.2
SIG00232: A51.6(A3) R51.1
SIG00233: A51.2(A1) DP53.1 IC51.17
SIG00234: A51.5(B3) R52.1
SIG00235: A51.1(B1) DP52.1 IC51.14
SIG00236: D53.C D54.C R53.2
SIG00372: D151.C R152.1
SIG00373: D152.A R153.1
SIG00374: D154.C R155.1
SIG00375: D155.A R156.1
SIG00376: CN153.1 DP157.1 L151.S
SIG00377: A101.P2(VSW) L101.1
SIG00378: D251.A R251.2 T101.5
SIG00379: R101.1 R102.2
SIG00380: D151.A D152.C D153.C IC151.7
SIG00381: C151.2 C152.2 C153.2 IC151.6 R151.2
SIG00382: C154.2 C155.2 D157.C D158.C R158.2 R159.1 R160.2
SIG00383: CN151.1 D157.A DP151.1 Q151.5 Q151.6 Q151.7 Q151.8 Q152.5 Q152.6 Q152.7 Q152.8 Q153.5 Q153.6 Q153.7 Q153.8
SIG00384: DP152.1 Q151.4 Q152.4 Q153.4 R152.2 R153.2 R154.2
SIG00385: D154.A D155.C D156.C IC151.5
SIG00386: DP155.1 Q154.4 Q155.4 Q156.4 R155.2 R156.2 R157.2
SIG00387: CN152.1 D158.A DP154.1 Q154.5 Q154.6 Q154.7 Q154.8 Q155.5 Q155.6 Q155.7 Q155.8 Q156.5 Q156.6 Q156.7 Q156.8
SIG00388: C201.2 C202.2 C203.2 IC201.6 R201.2
SIG00389: CN202.1 D208.A DP204.1 Q204.5 Q204.6 Q204.7 Q204.8 Q205.5 Q205.6 Q205.7 Q205.8 Q206.5 Q206.6 Q206.7 Q206.8
SIG00390: D205.A R206.1
SIG00391: C204.2 C205.2 D207.C D208.C R208.2 R209.1 R210.2
SIG00392: DP202.1 Q201.4 Q202.4 Q203.4 R202.2 R203.2 R204.2
SIG00393: D202.A R203.1
SIG00394: D204.C R205.1
SIG00395: D201.C R202.1
SIG00396: D201.A D202.C D203.C IC201.7
SIG00397: CN201.1 D207.A DP201.1 Q201.5 Q201.6 Q201.7 Q201.8 Q202.5 Q202.6 Q202.7 Q202.8 Q203.5 Q203.6 Q203.7 Q203.8
SIG00398: DP205.1 Q204.4 Q205.4 Q206.4 R205.2 R206.2 R207.2
SIG00399: CN203.1 DP207.1 L201.S
SIG00429: C256.1 R278.1
SIG00430: R268.2 R269.2 R273.1
SIG00431: IC251.11 R257.2
SIG00432: C252.2 C253.2 IC251.23 R256.2
SIG00433: IC251.9 R255.2
SIG00434: C255.2 DP259.1 IC251.15 R260.2 R265.2 R268.1
SIG00435: R280.1 R281.2
SIG00436: IC251.8 R254.2
SIG00437: IC251.7 R253.2
SIG00438: IC251.6 R252.2
SIG00439: C258.2 R284.1
SIG00440: R282.1 R283.2
SIG00441: R258.1 R259.2
SIG00442: IC251.10 R259.1
SIG00443: DP260.1 IC251.2 R266.1 R267.2
SIG00444: IC251.14 R263.1 R264.2 R265.1
SIG00445: IC251.13 R260.1 R261.2 R262.1
SIG00446: C257.1 C258.1 DP261.1 IC251.3 R278.2 R281.1 R282.2
SIG00447: R279.1 R280.2 R284.2
SIG00448: C256.2 C257.2 IC251.4 R277.2
SIG00449: R269.1 R270.1 R271.2
SIG00450: IC251.12 R271.1 R272.2
SIG003100: CN103.1 CN106.1 D101.A D102.C L101.2
SIG003101: A102.P2(VSW) CN101.1 CN104.1
SIG003102: A101.P1(VDC) A102.P1(VDC) D101.C T101.1
SIG003103: D204.A D205.C D206.C IC201.5
SIG006225: C303.2 DP302.1 IC301.3
SIG006226: C304.2 C305.2 IC301.1
SIG006227: D304.A R308.2
SIG006228: C307.2 C308.2 IC302.1
SIG006229: IC302.4 Q301.G R314.1 R315.2
SIG006230: DS301.4 R351.2
SIG006231: Q351.G R351.1 R352.2
SIG006232: R311.2 R312.2
SIG006233: R310.1 R311.1
SIG006234: R302.1 R303.1
SIG006235: R301.1 R302.2
SIG006236: R309.1 R310.2
SIG006237: D303.A R307.2
SIG006238: Q351.D R353.1
SIG006239: R303.2 R304.1
SIG006240: R305.1 R306.2
SIG006241: IC303.4 R357.2
SIG006242: R360.1 R361.1 R362.2
SIG006243: IC303.3 R354.2
SIG006244: R363.1 R364.1 R365.2
SIG006245: IC303.6 R363.2
SIG006246: R357.1 R358.1 R359.2
SIG006247: R354.1 R355.1 R356.2
SIG006248: IC303.5 R360.2
SIG006249: DS301.3 R317.2
SIG006250: C306.2 DP305.1 IC302.3
SIG006251: D303.C D304.C IC301.4
SIG006252: C302.2 D302.C DP301.1 IC301.5 R304.2 R305.2 R307.1
SIG006253: DS301.1 Q301.D R316.1
SIG006254: C310.2 DP304.1 IC302.5 R312.1 R313.2
SIG007201: C453.2 IC451.5 R454.1
SIG007202: C452.2 IC451.1 IC451.3 R453.2
SIG007203: C407.2 R412.1
SIG007204: R411.1 R417.2
SIG007205: IC401.3 R407.2
SIG007206: C401.2 C402.2 C403.2 F401.2 IC401.7 R401.1 T401.1
SIG007207: Q401.G R402.2 R403.2
SIG007208: IC401.6 R402.1
SIG007209: Q401.S R403.1 R404.2 R405.2 R406.2 R409.2
SIG007210: D402.C R408.2
SIG007211: D403.A T401.6
SIG007212: C411.2 D404.A D405.C IC402.2 IC402.4 R414.2 R416.2
SIG007213: C451.2 D451.C R451.2 R452.1
SIG007214: C406.2 IC401.2 R410.1 R411.2
SIG007215: C404.2 DP401.1 IC401.1 R408.1
SIG007216: D402.A R410.2 R412.2 T401.5
SIG007217: C405.2 DP402.1 IC401.5 R409.1
SIG007218: D401.A Q401.D T401.3
SIG007219: C402.1 C403.1 D401.C R401.2
SIG007220: C408.2 C409.2 D403.C D404.C DP403.1 IC402.3
SIG007221: C410.2 D405.A IC402.1 R413.2 R414.1
SIG007222: D451.A D451.NC T401.12 T401.13
SIG008125: C412.2 IC403.1 IC403.3 R415.2
SIGN364: C7.2 L2.1 R3.1 RY1.4 RY1.5
SS/EN: C251.2 DP251.1 IC251.5 R353.2
VREF_PSFB: C254.2 IC251.1 R258.2 R262.2 R263.2 R266.2 R270.2

Not connected (* = marked no-connect by the designer): CN1 2; CN102 1; CN105 1; D153 NC; D156 NC; D203 NC; D206 NC; IC1 1 4 5 8; IC151 1 8; IC201 1 8; IC251 16; IC303 7 10; IC403 4; IC451 4; T101 4 6 7; T151 1 2 3 4 5 6 7 8 9 10 11 12; T201 1 2 3 4 5 6 7 8 9 10 11 12; T401 2 7 10 11 14

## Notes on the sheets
sheet 1
- Primary
- Secondary
- 36:5:8:2
- x3
sheet 2
- Primary
- Secondary
- UVLO=275V
- UV_ON=170Vac
  UV_OFF=158Vac
- Input Voltage Monitoring
- VINUVLOFH
  VINUVLOFL
- VPFC_OUTUVLOFH
  VPFC_OUTUVLOFL
- PFC Output Voltage Monitoring
- delay=300ms
- delay=1s
sheet 3
- for Fan power supply
- Q501-Q504,Q506,Q507:
- 50V output
- for OUTPUT Sensing
sheet 5
- Primary
- Secondary
- 16T
- 3T
- 3T
- Q151-Q153:TPW2900ENH
- Q154-Q156:TPW2900ENH
- ¦A102 is connected
  to CN701 and CN702 of RD244-SCHEMATICS3
- C501-C503:
- 16T
- 3T
- 3T
- Q201-Q203:TPW2900ENH
- Q204-Q206:TPW2900ENH
- ¦A101 is connected
  to CN701 and CN702 of RD244-SCHEMATICS3
sheet 6
- ¦A51 is connected
  to CN601 and CN602 of RD244-SCHEMATICS2
- C51~C53:
sheet 7
- Input voltage sensing
